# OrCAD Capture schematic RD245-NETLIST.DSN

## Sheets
1 2: size A3
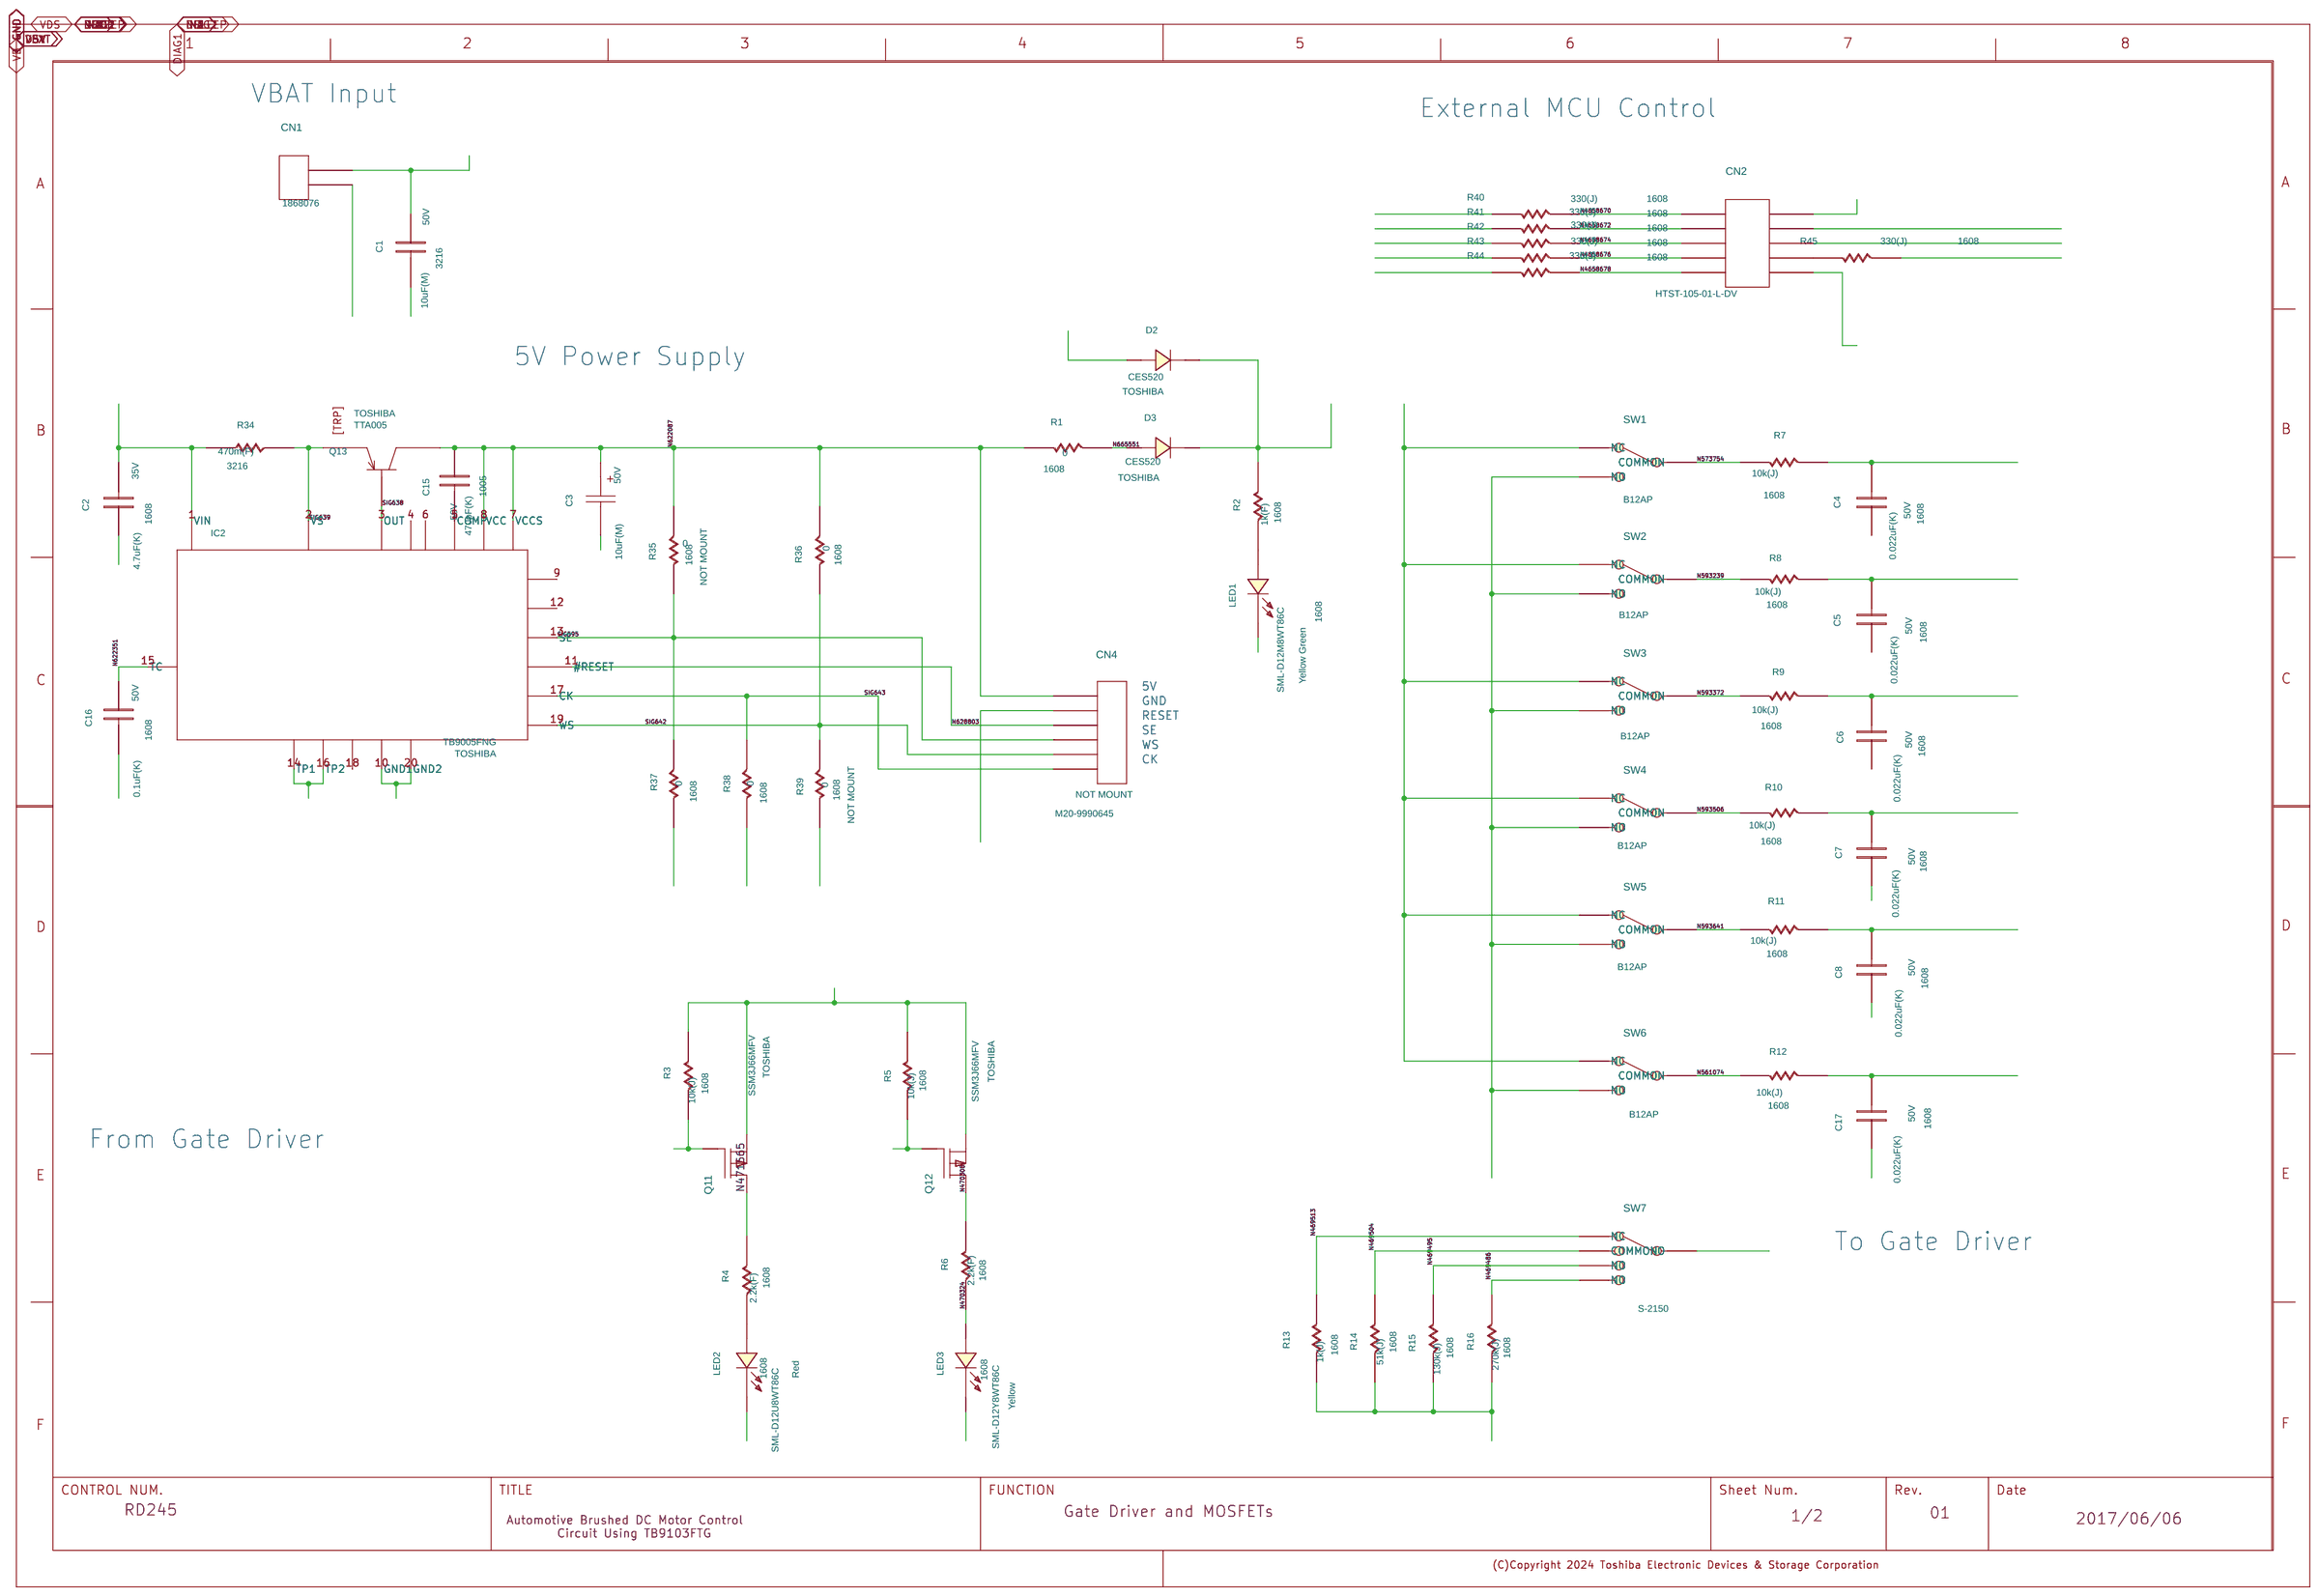
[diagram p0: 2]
2 1: size A3
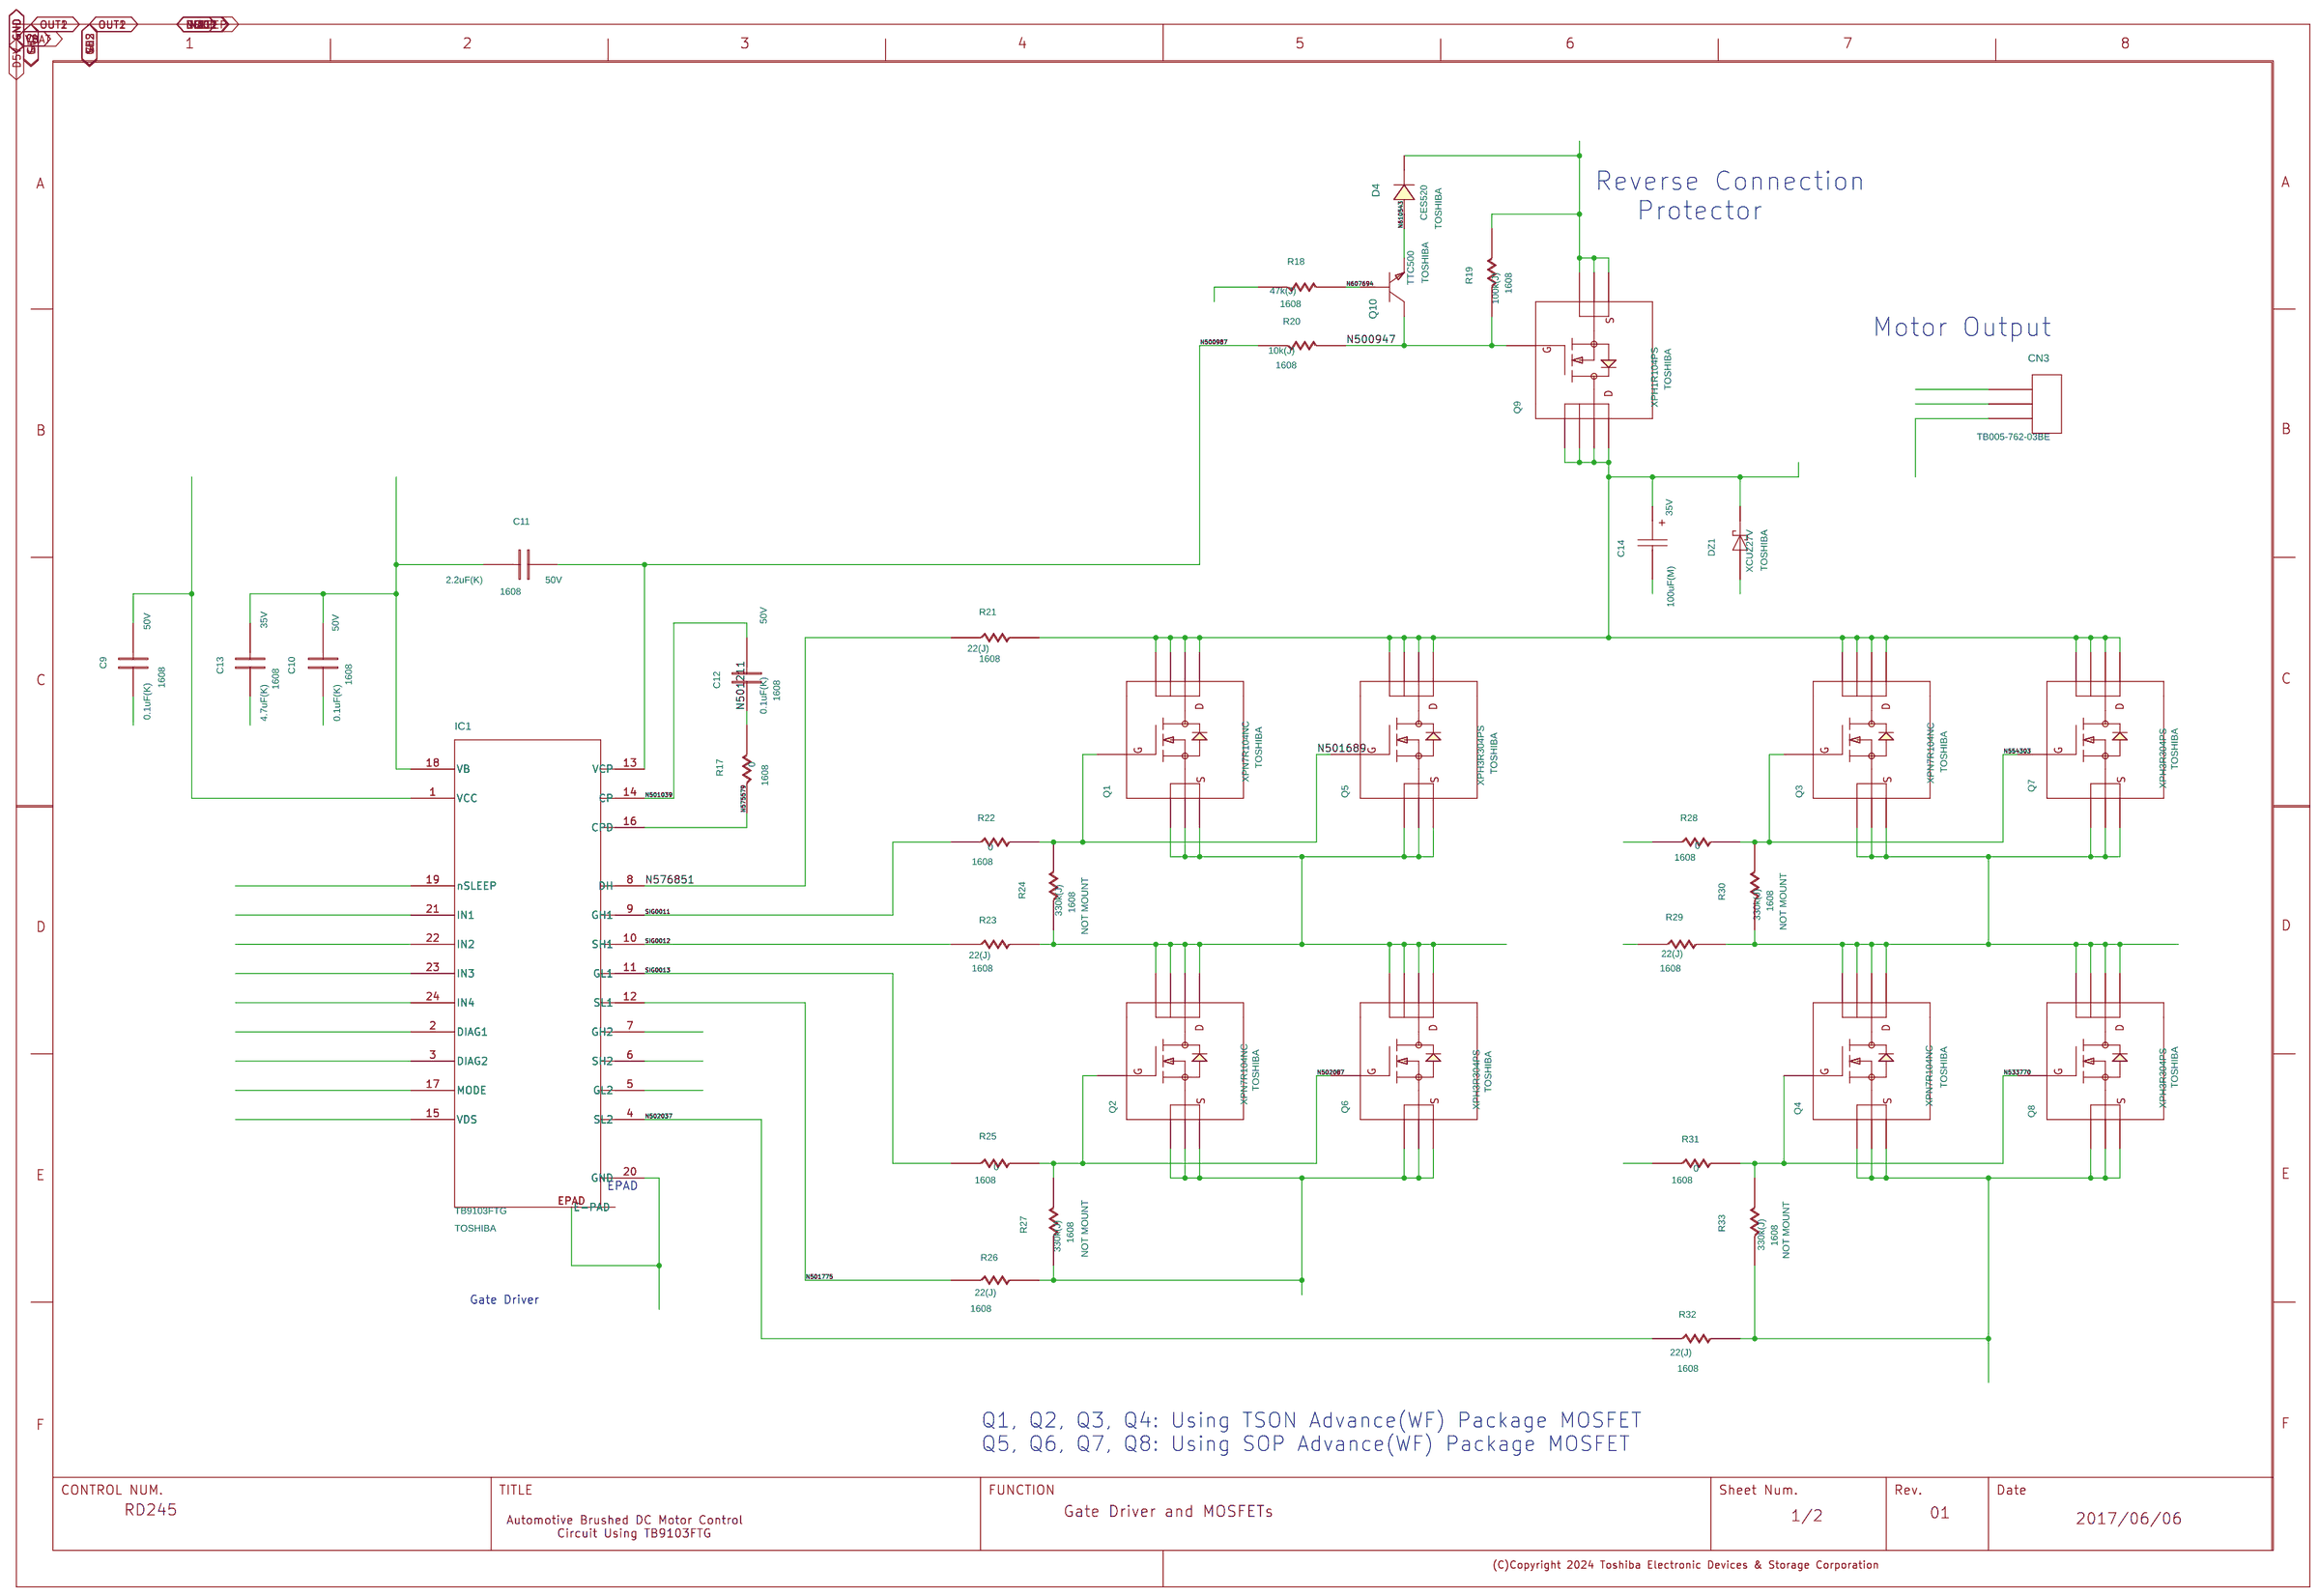
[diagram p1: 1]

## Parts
sheet 1
C9  C
C10  C
C11  C
C12  C
C13  C
C14  CP
CN3  TERMINAL-3P
D4  SBD
DZ1  SBD
IC1  TC241_3
Q1  MFNAC
Q2  MFNAC
Q3  MFNAC
Q4  MFNAC
Q5  MFNAC
Q6  MFNAC
Q7  MFNAC
Q8  MFNAC
Q9  MFNAC
Q10  BJT
R17  R
R18  R
R19  R
R20  R
R21  R
R22  R
R23  R
R24  R
R25  R
R26  R
R27  R
R28  R
R29  R
R30  R
R31  R
R32  R
R33  R
U?#1  WAKU_DEF100
sheet 2
C1  C
C2  C
C3  CP
C4  C
C5  C
C6  C
C7  C
C8  C
C15  C
C16  C
C17  C
CN1  TERMINAL-2P
CN2  PINHEADER-2x10
CN4  PINHEADER-1x6
D2  SBD
D3  SBD
IC2  TB9005FNG
LED1  LED
LED2  LED
LED3  LED
Q11  MOSFET
Q12  MOSFET
Q13  TRP
R1  R
R2  R
R3  R
R4  R
R5  R
R6  R
R7  R
R8  R
R9  R
R10  R
R11  R
R12  R
R13  R
R14  R
R15  R
R16  R
R34  R
R35  R
R36  R
R37  R
R38  R
R39  R
R40  R
R41  R
R42  R
R43  R
R44  R
R45  R
SW1  SW KEY-SPDT
SW2  SW KEY-SPDT
SW3  SW KEY-SPDT
SW4  SW KEY-SPDT
SW5  SW KEY-SPDT
SW6  SW KEY-SPDT
SW7  SW KEY-SPDT
U?#2  WAKU_DEF100

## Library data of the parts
C9 = C: ADSMODELNAME: s_ZRB18AR61E106ME01L; CAPACITANCETOLE: M; CDMASTERCADCELG: KC0167; CHIPSIZE: 1608; COMPONENTKIND: 0; COMPONENTNAME: C_C; COMPONENTTYPE: 4; FNLEADFREETHET1GT2GMCTH1: N_N_N; FUNCN: C_C; GCOUNT: 1; INSTANCENAME: INS530329; MAKER: TDK; MAXGCOUNT: 1; NOMINALCAPACITA: 10u; OUMECLASSIFICATION: ƒZƒ‰ƒ~ƒbƒNƒRƒ“ƒfƒ“ƒT; OUMEMAKER: MRT ºc»ì; OUMEMAKERKATAMEI: ZRB18AR61E106ME01L; QUADMODEL: CON_10U; RATEDVOLTAGE: 25; SIZECODESMD: 1608; TIME: 17:22:43; UPDATEDATE: 2021/07/08; UPDATETIME: 17:22:43; VAL1: 0.1uF(K); VAL2: 50V; VAL3: GCM188R71H104KA57J; VAL4: Murata
C10 = C: ADSMODELNAME: s_ZRB18AR61E106ME01L; CAPACITANCETOLE: M; CDMASTERCADCELG: KC0167; CHIPSIZE: 1608; COMPONENTKIND: 0; COMPONENTNAME: C_C; COMPONENTTYPE: 4; FNLEADFREETHET1GT2GMCTH1: N_N_N; FUNCN: C_C; GCOUNT: 1; INSTANCENAME: INS530425; MAKER: TDK; MAXGCOUNT: 1; NOMINALCAPACITA: 10u; OUMECLASSIFICATION: ƒZƒ‰ƒ~ƒbƒNƒRƒ“ƒfƒ“ƒT; OUMEMAKER: MRT ºc»ì; OUMEMAKERKATAMEI: ZRB18AR61E106ME01L; QUADMODEL: CON_10U; RATEDVOLTAGE: 25; SIZECODESMD: 1608; TIME: 17:22:43; UPDATEDATE: 2021/07/08; UPDATETIME: 17:22:43; VAL1: 0.1uF(K); VAL2: 50V; VAL3: GCM188R71H104KA57J; VAL4: Murata
C11 = C: ADSMODELNAME: s_ZRB18AR61E106ME01L; CAPACITANCETOLE: M; CDMASTERCADCELG: KC0167; CHIPSIZE: 1608; COMPONENTKIND: 0; COMPONENTNAME: C_C; COMPONENTTYPE: 4; FNLEADFREETHET1GT2GMCTH1: N_N_N; FUNCN: C_C; GCOUNT: 1; INSTANCENAME: INS530173; MAKER: TDK; MAXGCOUNT: 1; NOMINALCAPACITA: 10u; OUMECLASSIFICATION: ƒZƒ‰ƒ~ƒbƒNƒRƒ“ƒfƒ“ƒT; OUMEMAKER: MRT ºc»ì; OUMEMAKERKATAMEI: ZRB18AR61E106ME01L; QUADMODEL: CON_10U; RATEDVOLTAGE: 25; SIZECODESMD: 1608; TIME: 17:22:43; UPDATEDATE: 2021/07/08; UPDATETIME: 17:22:43; VAL1: 2.2uF(K); VAL2: 50V; VAL3: GRT188R61H225KE13D; VAL4: Murata
C12 = C: ADSMODELNAME: s_ZRB18AR61E106ME01L; CAPACITANCETOLE: M; CDMASTERCADCELG: KC0167; CHIPSIZE: 1608; COMPONENTKIND: 0; COMPONENTNAME: C_C; COMPONENTTYPE: 4; FNLEADFREETHET1GT2GMCTH1: N_N_N; FUNCN: C_C; GCOUNT: 1; INSTANCENAME: INS529943; MAKER: TDK; MAXGCOUNT: 1; NOMINALCAPACITA: 10u; OUMECLASSIFICATION: ƒZƒ‰ƒ~ƒbƒNƒRƒ“ƒfƒ“ƒT; OUMEMAKER: MRT ºc»ì; OUMEMAKERKATAMEI: ZRB18AR61E106ME01L; QUADMODEL: CON_10U; RATEDVOLTAGE: 25; SIZECODESMD: 1608; TIME: 17:22:43; UPDATEDATE: 2021/07/08; UPDATETIME: 17:22:43; VAL1: 0.1uF(K); VAL2: 50V; VAL3: GCM188R71H104KA57J; VAL4: Murata
C13 = C: ADSMODELNAME: s_ZRB18AR61E106ME01L; CAPACITANCETOLE: M; CDMASTERCADCELG: KC0167; CHIPSIZE: 1608; COMPONENTKIND: 0; COMPONENTNAME: C_C; COMPONENTTYPE: 4; FNLEADFREETHET1GT2GMCTH1: N_N_N; FUNCN: C_C; GCOUNT: 1; INSTANCENAME: INS647841; MAKER: TDK; MAXGCOUNT: 1; NOMINALCAPACITA: 10u; OUMECLASSIFICATION: ƒZƒ‰ƒ~ƒbƒNƒRƒ“ƒfƒ“ƒT; OUMEMAKER: MRT ºc»ì; OUMEMAKERKATAMEI: ZRB18AR61E106ME01L; QUADMODEL: CON_10U; RATEDVOLTAGE: 25; SIZECODESMD: 1608; TIME: 17:22:43; UPDATEDATE: 2021/07/08; UPDATETIME: 17:22:43; VAL1: 4.7uF(K); VAL2: 35V; VAL3: GRT188R6YA475KE13D; VAL4: Murata
C14 = CP: CAPACITANCETOLE: M; CDMASTERCADCELG: DC213N; CHIPSIZE: D35xL30; COMPONENTKIND: 0; COMPONENTNAME: CP_CP; COMPONENTTYPE: 4; FNLEADFREETHET1GT2GMCTH1: 9_N_N; FUNCN: CP_CP; GCOUNT: 1; INSTANCENAME: INS636800; MAKER: RUBYCON; MAXGCOUNT: 1; NOMINALCAPACITA: 330u; OUMECLASSIFICATION: ƒAƒ‹ƒ~“d‰ðƒRƒ“ƒfƒ“ƒT; OUMEMAKER: SIT ƒ‹ƒrƒRƒ“; OUMEMAKERKATAMEI: 450MXC330M35X40; OUMEPARTTYPE: C; QUADMODEL: CON_330U; RATEDVOLTAGE: 450; SAVECOUNT: 52; SIZECODESMD: DIP; TIME: 15:02:55; UPDATEDATE: 2006/10/03; UPDATETIME: 16:13:42; UPDATEUSER: fukuda-y; VAL1: 100uF(M); VAL2: 35V; VAL3: HHXD350ARA101MHA0G; VAL4: Chemi-Con
CN3 = CON3: COMPONENTKIND: 134; COMPONENTNAME: CON3_CON3; COMPONENTTYPE: 4; FUNCN: CON3_CON3; INSTANCENAME: INS530345; VAL2: 300V/30A; VAL3: TB005-762-03BE; VAL4: CUI Devices
D4 = DIODE_0: COMPONENTKIND: 103; COMPONENTNAME: DIODE_0_DIODE_0; COMPONENTTYPE: 4; FUNCN: DIODE_0_DIODE_0; INSTANCENAME: INS530245; USERCOMPTEXT3: TOSHIBA; VAL3: CES520; VAL4: TOSHIBA
DZ1 = SBD: COMPONENTKIND: 0; COMPONENTNAME: SBD_SBD; COMPONENTTYPE: 4; FUNCN: SBD_SBD; INSTANCENAME: INS530189; MAKER: TOSHIBA; TIME: 14:49:55; UPDATEDATE: 2006/10/04; UPDATETIME: 08:16:22; UPDATEUSER: fukuda-y; USERCOMPTEXT3: TOSHIBA; VAL3: XCUZ27V; VAL4: TOSHIBA
IC1 = TC241_3: COMPONENTKIND: 0; COMPONENTNAME: TC241_3_Graphic_Schematic_1_package; COMPONENTTYPE: 4; FUNCN: TC241_3_Graphic_Schematic_1_package; INSTANCENAME: cmp65; USERCOMPTEXT3: TOSHIBA; VAL1: GATE_DRIVER; VAL3: TB9103FTG
Q1 = MFNAC_23: COMPONENTKIND: 0; COMPONENTNAME: MFNAC_23_MFNAC_23; COMPONENTTYPE: 4; FUNCN: MFNAC_23_MFNAC_23; INSTANCENAME: INS529903; MAKER: TOSHIBA; TIME: 18:29:30; UPDATEDATE: 2008/08/26; UPDATETIME: 14:45:16; UPDATEUSER: 19990028; USERCOMPTEXT3: TOSHIBA; VAL3: XPN7R104NC; VAL4: TOSHIBA
Q2 = MFNAC_23: COMPONENTKIND: 0; COMPONENTNAME: MFNAC_23_MFNAC_23; COMPONENTTYPE: 4; FUNCN: MFNAC_23_MFNAC_23; INSTANCENAME: INS530205; MAKER: TOSHIBA; TIME: 18:29:30; UPDATEDATE: 2008/08/26; UPDATETIME: 14:45:16; UPDATEUSER: 19990028; USERCOMPTEXT3: TOSHIBA; VAL3: XPN7R104NC; VAL4: TOSHIBA
Q3 = MFNAC_23: COMPONENTKIND: 0; COMPONENTNAME: MFNAC_23_MFNAC_23; COMPONENTTYPE: 4; FUNCN: MFNAC_23_MFNAC_23; INSTANCENAME: INS533486; MAKER: TOSHIBA; TIME: 18:29:30; UPDATEDATE: 2008/08/26; UPDATETIME: 14:45:16; UPDATEUSER: 19990028; USERCOMPTEXT3: TOSHIBA; VAL3: XPN7R104NC; VAL4: TOSHIBA
Q4 = MFNAC_23: COMPONENTKIND: 0; COMPONENTNAME: MFNAC_23_MFNAC_23; COMPONENTTYPE: 4; FUNCN: MFNAC_23_MFNAC_23; INSTANCENAME: INS533696; MAKER: TOSHIBA; TIME: 18:29:30; UPDATEDATE: 2008/08/26; UPDATETIME: 14:45:16; UPDATEUSER: 19990028; USERCOMPTEXT3: TOSHIBA; VAL3: XPN7R104NC; VAL4: TOSHIBA
Q5 = MFNAC_23: COMPONENTKIND: 0; COMPONENTNAME: MFNAC_23_MFNAC_23; COMPONENTTYPE: 4; FUNCN: MFNAC_23_MFNAC_23; INSTANCENAME: INS530025; MAKER: TOSHIBA; TIME: 18:29:30; UPDATEDATE: 2008/08/26; UPDATETIME: 14:45:16; UPDATEUSER: 19990028; USERCOMPTEXT3: TOSHIBA; VAL3: XPH3R304PS; VAL4: TOSHIBA
Q6 = MFNAC_23: COMPONENTKIND: 0; COMPONENTNAME: MFNAC_23_MFNAC_23; COMPONENTTYPE: 4; FUNCN: MFNAC_23_MFNAC_23; INSTANCENAME: INS530385; MAKER: TOSHIBA; TIME: 18:29:30; UPDATEDATE: 2008/08/26; UPDATETIME: 14:45:16; UPDATEUSER: 19990028; USERCOMPTEXT3: TOSHIBA; VAL3: XPH3R304PS; VAL4: TOSHIBA
Q7 = MFNAC_23: COMPONENTKIND: 0; COMPONENTNAME: MFNAC_23_MFNAC_23; COMPONENTTYPE: 4; FUNCN: MFNAC_23_MFNAC_23; INSTANCENAME: INS533510; MAKER: TOSHIBA; TIME: 18:29:30; UPDATEDATE: 2008/08/26; UPDATETIME: 14:45:16; UPDATEUSER: 19990028; USERCOMPTEXT3: TOSHIBA; VAL3: XPH3R304PS; VAL4: TOSHIBA
Q8 = MFNAC_23: COMPONENTKIND: 0; COMPONENTNAME: MFNAC_23_MFNAC_23; COMPONENTTYPE: 4; FUNCN: MFNAC_23_MFNAC_23; INSTANCENAME: INS533720; MAKER: TOSHIBA; TIME: 18:29:30; UPDATEDATE: 2008/08/26; UPDATETIME: 14:45:16; UPDATEUSER: 19990028; USERCOMPTEXT3: TOSHIBA; VAL3: XPH3R304PS; VAL4: TOSHIBA
Q9 = MFNAC_23: COMPONENTKIND: 0; COMPONENTNAME: MFNAC_23_MFNAC_23; COMPONENTTYPE: 4; FUNCN: MFNAC_23_MFNAC_23; INSTANCENAME: INS529983; MAKER: TOSHIBA; TIME: 18:29:30; UPDATEDATE: 2008/08/26; UPDATETIME: 14:45:16; UPDATEUSER: 19990028; USERCOMPTEXT3: TOSHIBA; VAL3: XPH1R104PS; VAL4: TOSHIBA
Q10 = 2N1069_0: COMPONENTKIND: 102; COMPONENTNAME: 2N1069_0_2N1069_0; COMPONENTTYPE: 4; FUNCN: 2N1069_0_2N1069_0; INSTANCENAME: INS529959; USERCOMPTEXT3: TOSHIBA; VAL3: TTC500; VAL4: TOSHIBA
R17 = R: ADSMODELNAME: s_RL1632H_R001_JN; CDMASTERCADCELG: KC0020; CHIPSIZE: 3216; COMPONENTKIND: 0; COMPONENTNAME: R_R; COMPONENTTYPE: 4; FNLEADFREETHET1GT2GMCTH1: N_N_N; FUNCN: R_R; GCOUNT: 1; INSTANCENAME: INS529855; MAKER: KOA; MAXGCOUNT: 1; MOUNTINGFORMSMD: SMD; NOMINALRESISTAN: 1m; OUMECLASSIFICATION: \ÊÀpÅèïRí; OUMEMAKER: SSM iHÆ; OUMEMAKERKATAMEI: RL1632H-R001-JN; POWERRATING: 500m; QUADMODEL: RES_1M; RESISTANCETOLER: J; SIZECODESMD: 1608; TIME: 17:22:43; UPDATEDATE: 2021/07/08; UPDATETIME: 17:22:43; VAL1: 0; VAL3: RK73Z1JTTD; VAL4: KOA
R18 = R: ADSMODELNAME: s_RL1632H_R001_JN; CDMASTERCADCELG: KC0020; CHIPSIZE: 3216; COMPONENTKIND: 0; COMPONENTNAME: R_R; COMPONENTTYPE: 4; FNLEADFREETHET1GT2GMCTH1: N_N_N; FUNCN: R_R; GCOUNT: 1; INSTANCENAME: INS529871; MAKER: KOA; MAXGCOUNT: 1; MOUNTINGFORMSMD: SMD; NOMINALRESISTAN: 1m; OUMECLASSIFICATION: \ÊÀpÅèïRí; OUMEMAKER: SSM iHÆ; OUMEMAKERKATAMEI: RL1632H-R001-JN; POWERRATING: 500m; QUADMODEL: RES_1M; RESISTANCETOLER: J; SIZECODESMD: 1608; TIME: 17:22:43; UPDATEDATE: 2021/07/08; UPDATETIME: 17:22:43; VAL1: 47k(J); VAL2: 100mW; VAL3: RK73B1JTTD473J; VAL4: KOA
R19 = R: ADSMODELNAME: s_RL1632H_R001_JN; CDMASTERCADCELG: KC0020; CHIPSIZE: 3216; COMPONENTKIND: 0; COMPONENTNAME: R_R; COMPONENTTYPE: 4; FNLEADFREETHET1GT2GMCTH1: N_N_N; FUNCN: R_R; GCOUNT: 1; INSTANCENAME: INS530265; MAKER: KOA; MAXGCOUNT: 1; MOUNTINGFORMSMD: SMD; NOMINALRESISTAN: 1m; OUMECLASSIFICATION: \ÊÀpÅèïRí; OUMEMAKER: SSM iHÆ; OUMEMAKERKATAMEI: RL1632H-R001-JN; POWERRATING: 500m; QUADMODEL: RES_1M; RESISTANCETOLER: J; SIZECODESMD: 1608; TIME: 17:22:43; UPDATEDATE: 2021/07/08; UPDATETIME: 17:22:43; VAL1: 100k(J); VAL2: 100mW; VAL3: RK73B1JTTD104J; VAL4: KOA
R20 = R: ADSMODELNAME: s_RL1632H_R001_JN; CDMASTERCADCELG: KC0020; CHIPSIZE: 3216; COMPONENTKIND: 0; COMPONENTNAME: R_R; COMPONENTTYPE: 4; FNLEADFREETHET1GT2GMCTH1: N_N_N; FUNCN: R_R; GCOUNT: 1; INSTANCENAME: INS529887; MAKER: KOA; MAXGCOUNT: 1; MOUNTINGFORMSMD: SMD; NOMINALRESISTAN: 1m; OUMECLASSIFICATION: \ÊÀpÅèïRí; OUMEMAKER: SSM iHÆ; OUMEMAKERKATAMEI: RL1632H-R001-JN; POWERRATING: 500m; QUADMODEL: RES_1M; RESISTANCETOLER: J; SIZECODESMD: 1608; TIME: 17:22:43; UPDATEDATE: 2021/07/08; UPDATETIME: 17:22:43; VAL1: 10k(J); VAL2: 100mW; VAL3: RK73B1JTTD103J; VAL4: KOA
R21 = R: ADSMODELNAME: s_RL1632H_R001_JN; CDMASTERCADCELG: KC0020; CHIPSIZE: 3216; COMPONENTKIND: 0; COMPONENTNAME: R_R; COMPONENTTYPE: 4; FNLEADFREETHET1GT2GMCTH1: N_N_N; FUNCN: R_R; GCOUNT: 1; INSTANCENAME: INS575614; MAKER: KOA; MAXGCOUNT: 1; MOUNTINGFORMSMD: SMD; NOMINALRESISTAN: 1m; OUMECLASSIFICATION: \ÊÀpÅèïRí; OUMEMAKER: SSM iHÆ; OUMEMAKERKATAMEI: RL1632H-R001-JN; POWERRATING: 500m; QUADMODEL: RES_1M; RESISTANCETOLER: J; SIZECODESMD: 1608; TIME: 17:22:43; UPDATEDATE: 2021/07/08; UPDATETIME: 17:22:43; VAL1: 22(J); VAL2: 125mW; VAL3: RK73B1JTTD220J; VAL4: KOA
R22 = R: ADSMODELNAME: s_RL1632H_R001_JN; CDMASTERCADCELG: KC0020; CHIPSIZE: 3216; COMPONENTKIND: 0; COMPONENTNAME: R_R; COMPONENTTYPE: 4; FNLEADFREETHET1GT2GMCTH1: N_N_N; FUNCN: R_R; GCOUNT: 1; INSTANCENAME: INS530281; MAKER: KOA; MAXGCOUNT: 1; MOUNTINGFORMSMD: SMD; NOMINALRESISTAN: 1m; OUMECLASSIFICATION: \ÊÀpÅèïRí; OUMEMAKER: SSM iHÆ; OUMEMAKERKATAMEI: RL1632H-R001-JN; POWERRATING: 500m; QUADMODEL: RES_1M; RESISTANCETOLER: J; SIZECODESMD: 1608; TIME: 17:22:43; UPDATEDATE: 2021/07/08; UPDATETIME: 17:22:43; VAL1: 0; VAL3: RK73Z1JTTD; VAL4: KOA
R23 = R: ADSMODELNAME: s_RL1632H_R001_JN; CDMASTERCADCELG: KC0020; CHIPSIZE: 3216; COMPONENTKIND: 0; COMPONENTNAME: R_R; COMPONENTTYPE: 4; FNLEADFREETHET1GT2GMCTH1: N_N_N; FUNCN: R_R; GCOUNT: 1; INSTANCENAME: INS577102; MAKER: KOA; MAXGCOUNT: 1; MOUNTINGFORMSMD: SMD; NOMINALRESISTAN: 1m; OUMECLASSIFICATION: \ÊÀpÅèïRí; OUMEMAKER: SSM iHÆ; OUMEMAKERKATAMEI: RL1632H-R001-JN; POWERRATING: 500m; QUADMODEL: RES_1M; RESISTANCETOLER: J; SIZECODESMD: 1608; TIME: 17:22:43; UPDATEDATE: 2021/07/08; UPDATETIME: 17:22:43; VAL1: 22(J); VAL2: 125mW; VAL3: RK73B1JTTD220J; VAL4: KOA
R24 = R: ADSMODELNAME: s_RL1632H_R001_JN; CDMASTERCADCELG: KC0020; CHIPSIZE: 3216; COMPONENTKIND: 0; COMPONENTNAME: R_R; COMPONENTTYPE: 4; FNLEADFREETHET1GT2GMCTH1: N_N_N; FUNCN: R_R; GCOUNT: 1; INSTANCENAME: INS586735; MAKER: KOA; MAXGCOUNT: 1; MOUNTINGFORMSMD: SMD; NOMINALRESISTAN: 1m; NOTMOUNT: NOT MOUNT; OUMECLASSIFICATION: \ÊÀpÅèïRí; OUMEMAKER: SSM iHÆ; OUMEMAKERKATAMEI: RL1632H-R001-JN; POWERRATING: 500m; QUADMODEL: RES_1M; RESISTANCETOLER: J; SIZECODESMD: 1608; TIME: 17:22:43; UPDATEDATE: 2021/07/08; UPDATETIME: 17:22:43; VAL1: 330k(J); VAL2: 100mW; VAL3: RK73B1JTTD334J; VAL4: KOA
R25 = R: ADSMODELNAME: s_RL1632H_R001_JN; CDMASTERCADCELG: KC0020; CHIPSIZE: 3216; COMPONENTKIND: 0; COMPONENTNAME: R_R; COMPONENTTYPE: 4; FNLEADFREETHET1GT2GMCTH1: N_N_N; FUNCN: R_R; GCOUNT: 1; INSTANCENAME: INS530297; MAKER: KOA; MAXGCOUNT: 1; MOUNTINGFORMSMD: SMD; NOMINALRESISTAN: 1m; OUMECLASSIFICATION: \ÊÀpÅèïRí; OUMEMAKER: SSM iHÆ; OUMEMAKERKATAMEI: RL1632H-R001-JN; POWERRATING: 500m; QUADMODEL: RES_1M; RESISTANCETOLER: J; SIZECODESMD: 1608; TIME: 17:22:43; UPDATEDATE: 2021/07/08; UPDATETIME: 17:22:43; VAL1: 0; VAL3: RK73Z1JTTD; VAL4: KOA
R26 = R: ADSMODELNAME: s_RL1632H_R001_JN; CDMASTERCADCELG: KC0020; CHIPSIZE: 3216; COMPONENTKIND: 0; COMPONENTNAME: R_R; COMPONENTTYPE: 4; FNLEADFREETHET1GT2GMCTH1: N_N_N; FUNCN: R_R; GCOUNT: 1; INSTANCENAME: INS577602; MAKER: KOA; MAXGCOUNT: 1; MOUNTINGFORMSMD: SMD; NOMINALRESISTAN: 1m; OUMECLASSIFICATION: \ÊÀpÅèïRí; OUMEMAKER: SSM iHÆ; OUMEMAKERKATAMEI: RL1632H-R001-JN; POWERRATING: 500m; QUADMODEL: RES_1M; RESISTANCETOLER: J; SIZECODESMD: 1608; TIME: 17:22:43; UPDATEDATE: 2021/07/08; UPDATETIME: 17:22:43; VAL1: 22(J); VAL2: 125mW; VAL3: RK73B1JTTD220J; VAL4: KOA
R27 = R: ADSMODELNAME: s_RL1632H_R001_JN; CDMASTERCADCELG: KC0020; CHIPSIZE: 3216; COMPONENTKIND: 0; COMPONENTNAME: R_R; COMPONENTTYPE: 4; FNLEADFREETHET1GT2GMCTH1: N_N_N; FUNCN: R_R; GCOUNT: 1; INSTANCENAME: INS591774; MAKER: KOA; MAXGCOUNT: 1; MOUNTINGFORMSMD: SMD; NOMINALRESISTAN: 1m; NOTMOUNT: NOT MOUNT; OUMECLASSIFICATION: \ÊÀpÅèïRí; OUMEMAKER: SSM iHÆ; OUMEMAKERKATAMEI: RL1632H-R001-JN; POWERRATING: 500m; QUADMODEL: RES_1M; RESISTANCETOLER: J; SIZECODESMD: 1608; TIME: 17:22:43; UPDATEDATE: 2021/07/08; UPDATETIME: 17:22:43; VAL1: 330k(J); VAL2: 100mW; VAL3: RK73B1JTTD334J; VAL4: KOA
R28 = R: ADSMODELNAME: s_RL1632H_R001_JN; CDMASTERCADCELG: KC0020; CHIPSIZE: 3216; COMPONENTKIND: 0; COMPONENTNAME: R_R; COMPONENTTYPE: 4; FNLEADFREETHET1GT2GMCTH1: N_N_N; FUNCN: R_R; GCOUNT: 1; INSTANCENAME: INS533534; MAKER: KOA; MAXGCOUNT: 1; MOUNTINGFORMSMD: SMD; NOMINALRESISTAN: 1m; OUMECLASSIFICATION: \ÊÀpÅèïRí; OUMEMAKER: SSM iHÆ; OUMEMAKERKATAMEI: RL1632H-R001-JN; POWERRATING: 500m; QUADMODEL: RES_1M; RESISTANCETOLER: J; SIZECODESMD: 1608; TIME: 17:22:43; UPDATEDATE: 2021/07/08; UPDATETIME: 17:22:43; VAL1: 0; VAL3: RK73Z1JTTD; VAL4: KOA
R29 = R: ADSMODELNAME: s_RL1632H_R001_JN; CDMASTERCADCELG: KC0020; CHIPSIZE: 3216; COMPONENTKIND: 0; COMPONENTNAME: R_R; COMPONENTTYPE: 4; FNLEADFREETHET1GT2GMCTH1: N_N_N; FUNCN: R_R; GCOUNT: 1; INSTANCENAME: INS579870; MAKER: KOA; MAXGCOUNT: 1; MOUNTINGFORMSMD: SMD; NOMINALRESISTAN: 1m; OUMECLASSIFICATION: \ÊÀpÅèïRí; OUMEMAKER: SSM iHÆ; OUMEMAKERKATAMEI: RL1632H-R001-JN; POWERRATING: 500m; QUADMODEL: RES_1M; RESISTANCETOLER: J; SIZECODESMD: 1608; TIME: 17:22:43; UPDATEDATE: 2021/07/08; UPDATETIME: 17:22:43; VAL1: 22(J); VAL2: 125mW; VAL3: RK73B1JTTD220J; VAL4: KOA
R30 = R: ADSMODELNAME: s_RL1632H_R001_JN; CDMASTERCADCELG: KC0020; CHIPSIZE: 3216; COMPONENTKIND: 0; COMPONENTNAME: R_R; COMPONENTTYPE: 4; FNLEADFREETHET1GT2GMCTH1: N_N_N; FUNCN: R_R; GCOUNT: 1; INSTANCENAME: INS592756; MAKER: KOA; MAXGCOUNT: 1; MOUNTINGFORMSMD: SMD; NOMINALRESISTAN: 1m; NOTMOUNT: NOT MOUNT; OUMECLASSIFICATION: \ÊÀpÅèïRí; OUMEMAKER: SSM iHÆ; OUMEMAKERKATAMEI: RL1632H-R001-JN; POWERRATING: 500m; QUADMODEL: RES_1M; RESISTANCETOLER: J; SIZECODESMD: 1608; TIME: 17:22:43; UPDATEDATE: 2021/07/08; UPDATETIME: 17:22:43; VAL1: 330k(J); VAL2: 100mW; VAL3: RK73B1JTTD334J; VAL4: KOA
R31 = R: ADSMODELNAME: s_RL1632H_R001_JN; CDMASTERCADCELG: KC0020; CHIPSIZE: 3216; COMPONENTKIND: 0; COMPONENTNAME: R_R; COMPONENTTYPE: 4; FNLEADFREETHET1GT2GMCTH1: N_N_N; FUNCN: R_R; GCOUNT: 1; INSTANCENAME: INS533744; MAKER: KOA; MAXGCOUNT: 1; MOUNTINGFORMSMD: SMD; NOMINALRESISTAN: 1m; OUMECLASSIFICATION: \ÊÀpÅèïRí; OUMEMAKER: SSM iHÆ; OUMEMAKERKATAMEI: RL1632H-R001-JN; POWERRATING: 500m; QUADMODEL: RES_1M; RESISTANCETOLER: J; SIZECODESMD: 1608; TIME: 17:22:43; UPDATEDATE: 2021/07/08; UPDATETIME: 17:22:43; VAL1: 0; VAL3: RK73Z1JTTD; VAL4: KOA
R32 = R: ADSMODELNAME: s_RL1632H_R001_JN; CDMASTERCADCELG: KC0020; CHIPSIZE: 3216; COMPONENTKIND: 0; COMPONENTNAME: R_R; COMPONENTTYPE: 4; FNLEADFREETHET1GT2GMCTH1: N_N_N; FUNCN: R_R; GCOUNT: 1; INSTANCENAME: INS577624; MAKER: KOA; MAXGCOUNT: 1; MOUNTINGFORMSMD: SMD; NOMINALRESISTAN: 1m; OUMECLASSIFICATION: \ÊÀpÅèïRí; OUMEMAKER: SSM iHÆ; OUMEMAKERKATAMEI: RL1632H-R001-JN; POWERRATING: 500m; QUADMODEL: RES_1M; RESISTANCETOLER: J; SIZECODESMD: 1608; TIME: 17:22:43; UPDATEDATE: 2021/07/08; UPDATETIME: 17:22:43; VAL1: 22(J); VAL2: 125mW; VAL3: RK73B1JTTD220J; VAL4: KOA
R33 = R: ADSMODELNAME: s_RL1632H_R001_JN; CDMASTERCADCELG: KC0020; CHIPSIZE: 3216; COMPONENTKIND: 0; COMPONENTNAME: R_R; COMPONENTTYPE: 4; FNLEADFREETHET1GT2GMCTH1: N_N_N; FUNCN: R_R; GCOUNT: 1; INSTANCENAME: INS592511; MAKER: KOA; MAXGCOUNT: 1; MOUNTINGFORMSMD: SMD; NOMINALRESISTAN: 1m; NOTMOUNT: NOT MOUNT; OUMECLASSIFICATION: \ÊÀpÅèïRí; OUMEMAKER: SSM iHÆ; OUMEMAKERKATAMEI: RL1632H-R001-JN; POWERRATING: 500m; QUADMODEL: RES_1M; RESISTANCETOLER: J; SIZECODESMD: 1608; TIME: 17:22:43; UPDATEDATE: 2021/07/08; UPDATETIME: 17:22:43; VAL1: 330k(J); VAL2: 100mW; VAL3: RK73B1JTTD334J; VAL4: KOA
U?#1 = WAKU_DEF100_1: AUTHOR: t5459927; COMPONENTTYPE: 2; DATE: 2017/06/06; DESIGNED: TOSHIBA; DRAWINGNUMBER: RD245; FUNCTION: Gate Driver and MOSFETs; INSTANCENAME: INS636826; PAGENUMBER: 8; REVISION: 01; SHEETNUMBER: 1/2; SHTSAVECOUNT: 37; TITLE: Automotive Brushed DC Motor Control / Circuit Using TB9103FTG; UPDATEDATE: 2024/10/02; UPDATETIME: 10:40:02; UPDATEUSER: sptcae09
C1 = C: CDBNAME: C0805K_2; COMPONENTKIND: 0; COMPONENTNAME: C_C; COMPONENTTYPE: 4; FUNCN: C_C; INSTANCENAME: cmp141; SIZECODESMD: 3216; TIME: 17:22:43; UPDATEDATE: 2021/07/08; UPDATETIME: 17:22:43; VAL1: 10uF(M); VAL2: 50V; VAL3: GRT31CR61H106ME01L; VAL4: Murata
C2 = C: ADSMODELNAME: s_ZRB18AR61E106ME01L; CAPACITANCETOLE: M; CDMASTERCADCELG: KC0167; CHIPSIZE: 1608; COMPONENTKIND: 0; COMPONENTNAME: C_C; COMPONENTTYPE: 4; FNLEADFREETHET1GT2GMCTH1: N_N_N; FUNCN: C_C; GCOUNT: 1; INSTANCENAME: INS669941; MAKER: TDK; MAXGCOUNT: 1; NOMINALCAPACITA: 10u; OUMECLASSIFICATION: ƒZƒ‰ƒ~ƒbƒNƒRƒ“ƒfƒ“ƒT; OUMEMAKER: MRT ºc»ì; OUMEMAKERKATAMEI: ZRB18AR61E106ME01L; QUADMODEL: CON_10U; RATEDVOLTAGE: 25; SIZECODESMD: 1608; TIME: 17:22:43; UPDATEDATE: 2021/07/08; UPDATETIME: 17:22:43; VAL1: 4.7uF(K); VAL2: 35V; VAL3: GRT188R6YA475KE13D; VAL4: Murata
C3 = CP: CAPACITANCETOLE: M; CDMASTERCADCELG: DC213N; CHIPSIZE: D35xL30; COMPONENTKIND: 0; COMPONENTNAME: CP_CP; COMPONENTTYPE: 4; FNLEADFREETHET1GT2GMCTH1: 9_N_N; FUNCN: CP_CP; GCOUNT: 1; INSTANCENAME: INS634215; MAKER: RUBYCON; MAXGCOUNT: 1; NOMINALCAPACITA: 330u; OUMECLASSIFICATION: ƒAƒ‹ƒ~“d‰ðƒRƒ“ƒfƒ“ƒT; OUMEMAKER: SIT ƒ‹ƒrƒRƒ“; OUMEMAKERKATAMEI: 450MXC330M35X40; OUMEPARTTYPE: C; QUADMODEL: CON_330U; RATEDVOLTAGE: 450; SAVECOUNT: 52; SIZECODESMD: DIP; TIME: 15:02:55; UPDATEDATE: 2006/10/03; UPDATETIME: 16:13:42; UPDATEUSER: fukuda-y; VAL1: 10uF(M); VAL2: 50V; VAL3: HHXD500ARA100MF61G; VAL4: Chemi-Con
C4 = C: ADSMODELNAME: s_ZRB18AR61E106ME01L; CAPACITANCETOLE: M; CDMASTERCADCELG: KC0167; CHIPSIZE: 1608; COMPONENTKIND: 0; COMPONENTNAME: C_C; COMPONENTTYPE: 4; FNLEADFREETHET1GT2GMCTH1: N_N_N; FUNCN: C_C; GCOUNT: 1; INSTANCENAME: INS573773; MAKER: TDK; MAXGCOUNT: 1; NOMINALCAPACITA: 10u; OUMECLASSIFICATION: ƒZƒ‰ƒ~ƒbƒNƒRƒ“ƒfƒ“ƒT; OUMEMAKER: MRT ºc»ì; OUMEMAKERKATAMEI: ZRB18AR61E106ME01L; QUADMODEL: CON_10U; RATEDVOLTAGE: 25; SIZECODESMD: 1608; TIME: 17:22:43; UPDATEDATE: 2021/07/08; UPDATETIME: 17:22:43; VAL1: 0.022uF(K); VAL2: 50V; VAL3: GCM188R91H223KA37D; VAL4: Murata
C5 = C: ADSMODELNAME: s_ZRB18AR61E106ME01L; CAPACITANCETOLE: M; CDMASTERCADCELG: KC0167; CHIPSIZE: 1608; COMPONENTKIND: 0; COMPONENTNAME: C_C; COMPONENTTYPE: 4; FNLEADFREETHET1GT2GMCTH1: N_N_N; FUNCN: C_C; GCOUNT: 1; INSTANCENAME: INS658183; MAKER: TDK; MAXGCOUNT: 1; NOMINALCAPACITA: 10u; OUMECLASSIFICATION: ƒZƒ‰ƒ~ƒbƒNƒRƒ“ƒfƒ“ƒT; OUMEMAKER: MRT ºc»ì; OUMEMAKERKATAMEI: ZRB18AR61E106ME01L; QUADMODEL: CON_10U; RATEDVOLTAGE: 25; SIZECODESMD: 1608; TIME: 17:22:43; UPDATEDATE: 2021/07/08; UPDATETIME: 17:22:43; VAL1: 0.022uF(K); VAL2: 50V; VAL3: GCM188R91H223KA37D; VAL4: Murata
C6 = C: ADSMODELNAME: s_ZRB18AR61E106ME01L; CAPACITANCETOLE: M; CDMASTERCADCELG: KC0167; CHIPSIZE: 1608; COMPONENTKIND: 0; COMPONENTNAME: C_C; COMPONENTTYPE: 4; FNLEADFREETHET1GT2GMCTH1: N_N_N; FUNCN: C_C; GCOUNT: 1; INSTANCENAME: INS658285; MAKER: TDK; MAXGCOUNT: 1; NOMINALCAPACITA: 10u; OUMECLASSIFICATION: ƒZƒ‰ƒ~ƒbƒNƒRƒ“ƒfƒ“ƒT; OUMEMAKER: MRT ºc»ì; OUMEMAKERKATAMEI: ZRB18AR61E106ME01L; QUADMODEL: CON_10U; RATEDVOLTAGE: 25; SIZECODESMD: 1608; TIME: 17:22:43; UPDATEDATE: 2021/07/08; UPDATETIME: 17:22:43; VAL1: 0.022uF(K); VAL2: 50V; VAL3: GCM188R91H223KA37D; VAL4: Murata
C7 = C: ADSMODELNAME: s_ZRB18AR61E106ME01L; CAPACITANCETOLE: M; CDMASTERCADCELG: KC0167; CHIPSIZE: 1608; COMPONENTKIND: 0; COMPONENTNAME: C_C; COMPONENTTYPE: 4; FNLEADFREETHET1GT2GMCTH1: N_N_N; FUNCN: C_C; GCOUNT: 1; INSTANCENAME: INS658387; MAKER: TDK; MAXGCOUNT: 1; NOMINALCAPACITA: 10u; OUMECLASSIFICATION: ƒZƒ‰ƒ~ƒbƒNƒRƒ“ƒfƒ“ƒT; OUMEMAKER: MRT ºc»ì; OUMEMAKERKATAMEI: ZRB18AR61E106ME01L; QUADMODEL: CON_10U; RATEDVOLTAGE: 25; SIZECODESMD: 1608; TIME: 17:22:43; UPDATEDATE: 2021/07/08; UPDATETIME: 17:22:43; VAL1: 0.022uF(K); VAL2: 50V; VAL3: GCM188R91H223KA37D; VAL4: Murata
C8 = C: ADSMODELNAME: s_ZRB18AR61E106ME01L; CAPACITANCETOLE: M; CDMASTERCADCELG: KC0167; CHIPSIZE: 1608; COMPONENTKIND: 0; COMPONENTNAME: C_C; COMPONENTTYPE: 4; FNLEADFREETHET1GT2GMCTH1: N_N_N; FUNCN: C_C; GCOUNT: 1; INSTANCENAME: INS658489; MAKER: TDK; MAXGCOUNT: 1; NOMINALCAPACITA: 10u; OUMECLASSIFICATION: ƒZƒ‰ƒ~ƒbƒNƒRƒ“ƒfƒ“ƒT; OUMEMAKER: MRT ºc»ì; OUMEMAKERKATAMEI: ZRB18AR61E106ME01L; QUADMODEL: CON_10U; RATEDVOLTAGE: 25; SIZECODESMD: 1608; TIME: 17:22:43; UPDATEDATE: 2021/07/08; UPDATETIME: 17:22:43; VAL1: 0.022uF(K); VAL2: 50V; VAL3: GCM188R91H223KA37D; VAL4: Murata
C15 = C: CDBNAME: C0805K_2; COMPONENTKIND: 0; COMPONENTNAME: C_C; COMPONENTTYPE: 4; FUNCN: C_C; INSTANCENAME: cmp141; SIZECODESMD: 1005; TIME: 17:22:43; UPDATEDATE: 2021/07/08; UPDATETIME: 17:22:43; VAL1: 470pF(K); VAL2: 50V; VAL3: GCM155R71H471KA37J; VAL4: Murata
C16 = C: CDBNAME: C0805K_3; COMPONENTKIND: 0; COMPONENTNAME: C_C; COMPONENTTYPE: 4; FUNCN: C_C; INSTANCENAME: cmp152; SIZECODESMD: 1608; TIME: 17:22:43; UPDATEDATE: 2021/07/08; UPDATETIME: 17:22:43; VAL1: 0.1uF(K); VAL2: 50V; VAL3: GCM188R71H104KA57J; VAL4: Murata
C17 = C: ADSMODELNAME: s_ZRB18AR61E106ME01L; CAPACITANCETOLE: M; CDMASTERCADCELG: KC0167; CHIPSIZE: 1608; COMPONENTKIND: 0; COMPONENTNAME: C_C; COMPONENTTYPE: 4; FNLEADFREETHET1GT2GMCTH1: N_N_N; FUNCN: C_C; GCOUNT: 1; INSTANCENAME: INS658591; MAKER: TDK; MAXGCOUNT: 1; NOMINALCAPACITA: 10u; OUMECLASSIFICATION: ƒZƒ‰ƒ~ƒbƒNƒRƒ“ƒfƒ“ƒT; OUMEMAKER: MRT ºc»ì; OUMEMAKERKATAMEI: ZRB18AR61E106ME01L; QUADMODEL: CON_10U; RATEDVOLTAGE: 25; SIZECODESMD: 1608; TIME: 17:22:43; UPDATEDATE: 2021/07/08; UPDATETIME: 17:22:43; VAL1: 0.022uF(K); VAL2: 50V; VAL3: GCM188R91H223KA37D; VAL4: Murata
CN1 = CON2: COMPONENTKIND: 134; COMPONENTNAME: CON2_CON2; COMPONENTTYPE: 4; FUNCN: CON2_CON2; INSTANCENAME: INS451962; VAL2: 500V/32A; VAL3: 1868076; VAL4: Phoenix
CN2 = CON10A: COMPONENTKIND: 134; COMPONENTNAME: CON10A_CON10A; COMPONENTTYPE: 4; FUNCN: CON10A_CON10A; INSTANCENAME: INS465841; VAL3: HTST-105-01-L-DV; VAL4: Samtec
CN4 = CON6: COMPONENTKIND: 134; COMPONENTNAME: CON6_CON6; COMPONENTTYPE: 4; FUNCN: CON6_CON6; INSTANCENAME: INS655764; NOTMOUNT: NOT MOUNT; VAL3: M20-9990645; VAL4: Harwin
D2 = DIODE_0: COMPONENTKIND: 103; COMPONENTNAME: DIODE_0_DIODE_0; COMPONENTTYPE: 4; FUNCN: DIODE_0_DIODE_0; INSTANCENAME: INS572955; USERCOMPTEXT3: TOSHIBA; VAL3: CES520; VAL4: TOSHIBA
D3 = DIODE_0: COMPONENTKIND: 103; COMPONENTNAME: DIODE_0_DIODE_0; COMPONENTTYPE: 4; FUNCN: DIODE_0_DIODE_0; INSTANCENAME: INS573569; USERCOMPTEXT3: TOSHIBA; VAL3: CES520; VAL4: TOSHIBA
IC2 = TB9005FNG_1: COMPONENTKIND: 0; COMPONENTNAME: TB9005FNG_1_TB9005FNG_1; COMPONENTTYPE: 4; FUNCN: TB9005FNG_1_TB9005FNG_1; INSTANCENAME: INS622199; SAVECOUNT: 3; TIME: 17:22:42; UPDATEDATE: 2021/07/13; UPDATETIME: 09:48:39; USERCOMPTEXT3: TOSHIBA; VAL1: LINEAR IC; VAL4: TOSHIBA
LED1 = LED_2: COMPONENTKIND: 103; COMPONENTNAME: LED_2_LED_2; COMPONENTTYPE: 4; FUNCN: LED_2_LED_2; INSTANCENAME: INS453112; SIZECODESMD: 1608; VAL1: Yellow Green; VAL3: SML-D12M8WT86C; VAL4: Rohm
LED2 = LED_2: COMPONENTKIND: 103; COMPONENTNAME: LED_2_LED_2; COMPONENTTYPE: 4; FUNCN: LED_2_LED_2; INSTANCENAME: INS496113; SIZECODESMD: 1608; VAL1: Red; VAL3: SML-D12U8WT86C; VAL4: Rohm
LED3 = LED_2: COMPONENTKIND: 103; COMPONENTNAME: LED_2_LED_2; COMPONENTTYPE: 4; FUNCN: LED_2_LED_2; INSTANCENAME: INS496225; SIZECODESMD: 1608; VAL1: Yellow; VAL3: SML-D12Y8WT86C; VAL4: Rohm
Q11 = ZVP0545_TO_0: COMPONENTKIND: 102; COMPONENTNAME: ZVP0545_TO_0_ZVP0545_TO_0; COMPONENTTYPE: 4; FUNCN: ZVP0545_TO_0_ZVP0545_TO_0; INSTANCENAME: INS493920; USERCOMPTEXT3: TOSHIBA; VAL3: SSM3J66MFV; VAL4: TOSHIBA
Q12 = ZVP0545_TO_0: COMPONENTKIND: 102; COMPONENTNAME: ZVP0545_TO_0_ZVP0545_TO_0; COMPONENTTYPE: 4; FUNCN: ZVP0545_TO_0_ZVP0545_TO_0; INSTANCENAME: INS494083; USERCOMPTEXT3: TOSHIBA; VAL3: SSM3J66MFV; VAL4: TOSHIBA
Q13 = TRP: CDBNAME: TTA005; COMPONENTKIND: 0; COMPONENTNAME: TRP_TRP; COMPONENTTYPE: 4; FUNCN: TRP_TRP; INSTANCENAME: cmp138; TIME: 17:22:43; UPDATEDATE: 2021/07/08; UPDATETIME: 17:22:43; USERCOMPTEXT3: TOSHIBA; VAL3: TTA005; VAL4: TOSHIBA
R1 = R: ADSMODELNAME: s_RL1632H_R001_JN; CDMASTERCADCELG: KC0020; CHIPSIZE: 3216; COMPONENTKIND: 0; COMPONENTNAME: R_R; COMPONENTTYPE: 4; FNLEADFREETHET1GT2GMCTH1: N_N_N; FUNCN: R_R; GCOUNT: 1; INSTANCENAME: INS575096; MAKER: KOA; MAXGCOUNT: 1; MOUNTINGFORMSMD: SMD; NOMINALRESISTAN: 1m; OUMECLASSIFICATION: \ÊÀpÅèïRí; OUMEMAKER: SSM iHÆ; OUMEMAKERKATAMEI: RL1632H-R001-JN; POWERRATING: 500m; QUADMODEL: RES_1M; RESISTANCETOLER: J; SIZECODESMD: 1608; TIME: 17:22:43; UPDATEDATE: 2021/07/08; UPDATETIME: 17:22:43; VAL1: 0; VAL3: RK73Z1JTTD; VAL4: KOA
R2 = R: ADSMODELNAME: s_RL1632H_R001_JN; CDMASTERCADCELG: KC0020; CHIPSIZE: 3216; COMPONENTKIND: 0; COMPONENTNAME: R_R; COMPONENTTYPE: 4; FNLEADFREETHET1GT2GMCTH1: N_N_N; FUNCN: R_R; GCOUNT: 1; INSTANCENAME: INS454341; MAKER: KOA; MAXGCOUNT: 1; MOUNTINGFORMSMD: SMD; NOMINALRESISTAN: 1m; OUMECLASSIFICATION: \ÊÀpÅèïRí; OUMEMAKER: SSM iHÆ; OUMEMAKERKATAMEI: RL1632H-R001-JN; POWERRATING: 500m; QUADMODEL: RES_1M; RESISTANCETOLER: J; SIZECODESMD: 1608; TIME: 17:22:43; UPDATEDATE: 2021/07/08; UPDATETIME: 17:22:43; VAL1: 1k(F); VAL2: 125mW; VAL3: RK73H1JTTD1001F; VAL4: KOA
R3 = R: ADSMODELNAME: s_RL1632H_R001_JN; CDMASTERCADCELG: KC0020; CHIPSIZE: 3216; COMPONENTKIND: 0; COMPONENTNAME: R_R; COMPONENTTYPE: 4; FNLEADFREETHET1GT2GMCTH1: N_N_N; FUNCN: R_R; GCOUNT: 1; INSTANCENAME: INS486568; MAKER: KOA; MAXGCOUNT: 1; MOUNTINGFORMSMD: SMD; NOMINALRESISTAN: 1m; OUMECLASSIFICATION: \ÊÀpÅèïRí; OUMEMAKER: SSM iHÆ; OUMEMAKERKATAMEI: RL1632H-R001-JN; POWERRATING: 500m; QUADMODEL: RES_1M; RESISTANCETOLER: J; SIZECODESMD: 1608; TIME: 17:22:43; UPDATEDATE: 2021/07/08; UPDATETIME: 17:22:43; VAL1: 10k(J); VAL2: 100mW; VAL3: RK73B1JTTD103J; VAL4: KOA
R4 = R: ADSMODELNAME: s_RL1632H_R001_JN; CDMASTERCADCELG: KC0020; CHIPSIZE: 3216; COMPONENTKIND: 0; COMPONENTNAME: R_R; COMPONENTTYPE: 4; FNLEADFREETHET1GT2GMCTH1: N_N_N; FUNCN: R_R; GCOUNT: 1; INSTANCENAME: INS471567; MAKER: KOA; MAXGCOUNT: 1; MOUNTINGFORMSMD: SMD; NOMINALRESISTAN: 1m; OUMECLASSIFICATION: \ÊÀpÅèïRí; OUMEMAKER: SSM iHÆ; OUMEMAKERKATAMEI: RL1632H-R001-JN; POWERRATING: 500m; QUADMODEL: RES_1M; RESISTANCETOLER: J; SIZECODESMD: 1608; TIME: 17:22:43; UPDATEDATE: 2021/07/08; UPDATETIME: 17:22:43; VAL1: 2.2k(F); VAL2: 100mW; VAL3: RK73H1JTTD2201F; VAL4: KOA
R5 = R: ADSMODELNAME: s_RL1632H_R001_JN; CDMASTERCADCELG: KC0020; CHIPSIZE: 3216; COMPONENTKIND: 0; COMPONENTNAME: R_R; COMPONENTTYPE: 4; FNLEADFREETHET1GT2GMCTH1: N_N_N; FUNCN: R_R; GCOUNT: 1; INSTANCENAME: INS487189; MAKER: KOA; MAXGCOUNT: 1; MOUNTINGFORMSMD: SMD; NOMINALRESISTAN: 1m; OUMECLASSIFICATION: \ÊÀpÅèïRí; OUMEMAKER: SSM iHÆ; OUMEMAKERKATAMEI: RL1632H-R001-JN; POWERRATING: 500m; QUADMODEL: RES_1M; RESISTANCETOLER: J; SIZECODESMD: 1608; TIME: 17:22:43; UPDATEDATE: 2021/07/08; UPDATETIME: 17:22:43; VAL1: 10k(J); VAL2: 100mW; VAL3: RK73B1JTTD103J; VAL4: KOA
R6 = R: ADSMODELNAME: s_RL1632H_R001_JN; CDMASTERCADCELG: KC0020; CHIPSIZE: 3216; COMPONENTKIND: 0; COMPONENTNAME: R_R; COMPONENTTYPE: 4; FNLEADFREETHET1GT2GMCTH1: N_N_N; FUNCN: R_R; GCOUNT: 1; INSTANCENAME: INS470310; MAKER: KOA; MAXGCOUNT: 1; MOUNTINGFORMSMD: SMD; NOMINALRESISTAN: 1m; OUMECLASSIFICATION: \ÊÀpÅèïRí; OUMEMAKER: SSM iHÆ; OUMEMAKERKATAMEI: RL1632H-R001-JN; POWERRATING: 500m; QUADMODEL: RES_1M; RESISTANCETOLER: J; SIZECODESMD: 1608; TIME: 17:22:43; UPDATEDATE: 2021/07/08; UPDATETIME: 17:22:43; VAL1: 2.2k(F); VAL2: 100mW; VAL3: RK73H1JTTD2201F; VAL4: KOA
R7 = R: ADSMODELNAME: s_RL1632H_R001_JN; CDMASTERCADCELG: KC0020; CHIPSIZE: 3216; COMPONENTKIND: 0; COMPONENTNAME: R_R; COMPONENTTYPE: 4; FNLEADFREETHET1GT2GMCTH1: N_N_N; FUNCN: R_R; GCOUNT: 1; INSTANCENAME: INS515728; MAKER: KOA; MAXGCOUNT: 1; MOUNTINGFORMSMD: SMD; NOMINALRESISTAN: 1m; OUMECLASSIFICATION: \ÊÀpÅèïRí; OUMEMAKER: SSM iHÆ; OUMEMAKERKATAMEI: RL1632H-R001-JN; POWERRATING: 500m; QUADMODEL: RES_1M; RESISTANCETOLER: J; SIZECODESMD: 1608; TIME: 17:22:43; UPDATEDATE: 2021/07/08; UPDATETIME: 17:22:43; VAL1: 10k(J); VAL2: 100mW; VAL3: RK73B1JTTD103J; VAL4: KOA
R8 = R: ADSMODELNAME: s_RL1632H_R001_JN; CDMASTERCADCELG: KC0020; CHIPSIZE: 3216; COMPONENTKIND: 0; COMPONENTNAME: R_R; COMPONENTTYPE: 4; FNLEADFREETHET1GT2GMCTH1: N_N_N; FUNCN: R_R; GCOUNT: 1; INSTANCENAME: INS593225; MAKER: KOA; MAXGCOUNT: 1; MOUNTINGFORMSMD: SMD; NOMINALRESISTAN: 1m; OUMECLASSIFICATION: \ÊÀpÅèïRí; OUMEMAKER: SSM iHÆ; OUMEMAKERKATAMEI: RL1632H-R001-JN; POWERRATING: 500m; QUADMODEL: RES_1M; RESISTANCETOLER: J; SIZECODESMD: 1608; TIME: 17:22:43; UPDATEDATE: 2021/07/08; UPDATETIME: 17:22:43; VAL1: 10k(J); VAL2: 100mW; VAL3: RK73B1JTTD103J; VAL4: KOA
R9 = R: ADSMODELNAME: s_RL1632H_R001_JN; CDMASTERCADCELG: KC0020; CHIPSIZE: 3216; COMPONENTKIND: 0; COMPONENTNAME: R_R; COMPONENTTYPE: 4; FNLEADFREETHET1GT2GMCTH1: N_N_N; FUNCN: R_R; GCOUNT: 1; INSTANCENAME: INS593358; MAKER: KOA; MAXGCOUNT: 1; MOUNTINGFORMSMD: SMD; NOMINALRESISTAN: 1m; OUMECLASSIFICATION: \ÊÀpÅèïRí; OUMEMAKER: SSM iHÆ; OUMEMAKERKATAMEI: RL1632H-R001-JN; POWERRATING: 500m; QUADMODEL: RES_1M; RESISTANCETOLER: J; SIZECODESMD: 1608; TIME: 17:22:43; UPDATEDATE: 2021/07/08; UPDATETIME: 17:22:43; VAL1: 10k(J); VAL2: 100mW; VAL3: RK73B1JTTD103J; VAL4: KOA
R10 = R: ADSMODELNAME: s_RL1632H_R001_JN; CDMASTERCADCELG: KC0020; CHIPSIZE: 3216; COMPONENTKIND: 0; COMPONENTNAME: R_R; COMPONENTTYPE: 4; FNLEADFREETHET1GT2GMCTH1: N_N_N; FUNCN: R_R; GCOUNT: 1; INSTANCENAME: INS593492; MAKER: KOA; MAXGCOUNT: 1; MOUNTINGFORMSMD: SMD; NOMINALRESISTAN: 1m; OUMECLASSIFICATION: \ÊÀpÅèïRí; OUMEMAKER: SSM iHÆ; OUMEMAKERKATAMEI: RL1632H-R001-JN; POWERRATING: 500m; QUADMODEL: RES_1M; RESISTANCETOLER: J; SIZECODESMD: 1608; TIME: 17:22:43; UPDATEDATE: 2021/07/08; UPDATETIME: 17:22:43; VAL1: 10k(J); VAL2: 100mW; VAL3: RK73B1JTTD103J; VAL4: KOA
R11 = R: ADSMODELNAME: s_RL1632H_R001_JN; CDMASTERCADCELG: KC0020; CHIPSIZE: 3216; COMPONENTKIND: 0; COMPONENTNAME: R_R; COMPONENTTYPE: 4; FNLEADFREETHET1GT2GMCTH1: N_N_N; FUNCN: R_R; GCOUNT: 1; INSTANCENAME: INS593627; MAKER: KOA; MAXGCOUNT: 1; MOUNTINGFORMSMD: SMD; NOMINALRESISTAN: 1m; OUMECLASSIFICATION: \ÊÀpÅèïRí; OUMEMAKER: SSM iHÆ; OUMEMAKERKATAMEI: RL1632H-R001-JN; POWERRATING: 500m; QUADMODEL: RES_1M; RESISTANCETOLER: J; SIZECODESMD: 1608; TIME: 17:22:43; UPDATEDATE: 2021/07/08; UPDATETIME: 17:22:43; VAL1: 10k(J); VAL2: 100mW; VAL3: RK73B1JTTD103J; VAL4: KOA
R12 = R: ADSMODELNAME: s_RL1632H_R001_JN; CDMASTERCADCELG: KC0020; CHIPSIZE: 3216; COMPONENTKIND: 0; COMPONENTNAME: R_R; COMPONENTTYPE: 4; FNLEADFREETHET1GT2GMCTH1: N_N_N; FUNCN: R_R; GCOUNT: 1; INSTANCENAME: INS561051; MAKER: KOA; MAXGCOUNT: 1; MOUNTINGFORMSMD: SMD; NOMINALRESISTAN: 1m; OUMECLASSIFICATION: \ÊÀpÅèïRí; OUMEMAKER: SSM iHÆ; OUMEMAKERKATAMEI: RL1632H-R001-JN; POWERRATING: 500m; QUADMODEL: RES_1M; RESISTANCETOLER: J; SIZECODESMD: 1608; TIME: 17:22:43; UPDATEDATE: 2021/07/08; UPDATETIME: 17:22:43; VAL1: 10k(J); VAL2: 100mW; VAL3: RK73B1JTTD103J; VAL4: KOA
R13 = R: ADSMODELNAME: s_RL1632H_R001_JN; CDMASTERCADCELG: KC0020; CHIPSIZE: 3216; COMPONENTKIND: 0; COMPONENTNAME: R_R; COMPONENTTYPE: 4; FNLEADFREETHET1GT2GMCTH1: N_N_N; FUNCN: R_R; GCOUNT: 1; INSTANCENAME: INS467908; MAKER: KOA; MAXGCOUNT: 1; MOUNTINGFORMSMD: SMD; NOMINALRESISTAN: 1m; OUMECLASSIFICATION: \ÊÀpÅèïRí; OUMEMAKER: SSM iHÆ; OUMEMAKERKATAMEI: RL1632H-R001-JN; POWERRATING: 500m; QUADMODEL: RES_1M; RESISTANCETOLER: J; SIZECODESMD: 1608; TIME: 17:22:43; UPDATEDATE: 2021/07/08; UPDATETIME: 17:22:43; VAL1: 1k(J); VAL2: 125mW; VAL3: RK73B1JTTD102J; VAL4: KOA
R14 = R: ADSMODELNAME: s_RL1632H_R001_JN; CDMASTERCADCELG: KC0020; CHIPSIZE: 3216; COMPONENTKIND: 0; COMPONENTNAME: R_R; COMPONENTTYPE: 4; FNLEADFREETHET1GT2GMCTH1: N_N_N; FUNCN: R_R; GCOUNT: 1; INSTANCENAME: INS467930; MAKER: KOA; MAXGCOUNT: 1; MOUNTINGFORMSMD: SMD; NOMINALRESISTAN: 1m; OUMECLASSIFICATION: \ÊÀpÅèïRí; OUMEMAKER: SSM iHÆ; OUMEMAKERKATAMEI: RL1632H-R001-JN; POWERRATING: 500m; QUADMODEL: RES_1M; RESISTANCETOLER: J; SIZECODESMD: 1608; TIME: 17:22:43; UPDATEDATE: 2021/07/08; UPDATETIME: 17:22:43; VAL1: 51k(J); VAL2: 100mW; VAL3: RK73B1JTTD513J; VAL4: KOA
R15 = R: ADSMODELNAME: s_RL1632H_R001_JN; CDMASTERCADCELG: KC0020; CHIPSIZE: 3216; COMPONENTKIND: 0; COMPONENTNAME: R_R; COMPONENTTYPE: 4; FNLEADFREETHET1GT2GMCTH1: N_N_N; FUNCN: R_R; GCOUNT: 1; INSTANCENAME: INS467952; MAKER: KOA; MAXGCOUNT: 1; MOUNTINGFORMSMD: SMD; NOMINALRESISTAN: 1m; OUMECLASSIFICATION: \ÊÀpÅèïRí; OUMEMAKER: SSM iHÆ; OUMEMAKERKATAMEI: RL1632H-R001-JN; POWERRATING: 500m; QUADMODEL: RES_1M; RESISTANCETOLER: J; SIZECODESMD: 1608; TIME: 17:22:43; UPDATEDATE: 2021/07/08; UPDATETIME: 17:22:43; VAL1: 130k(J); VAL2: 100mW; VAL3: RK73B1JTTD134J; VAL4: KOA
R16 = R: ADSMODELNAME: s_RL1632H_R001_JN; CDMASTERCADCELG: KC0020; CHIPSIZE: 3216; COMPONENTKIND: 0; COMPONENTNAME: R_R; COMPONENTTYPE: 4; FNLEADFREETHET1GT2GMCTH1: N_N_N; FUNCN: R_R; GCOUNT: 1; INSTANCENAME: INS467974; MAKER: KOA; MAXGCOUNT: 1; MOUNTINGFORMSMD: SMD; NOMINALRESISTAN: 1m; OUMECLASSIFICATION: \ÊÀpÅèïRí; OUMEMAKER: SSM iHÆ; OUMEMAKERKATAMEI: RL1632H-R001-JN; POWERRATING: 500m; QUADMODEL: RES_1M; RESISTANCETOLER: J; SIZECODESMD: 1608; TIME: 17:22:43; UPDATEDATE: 2021/07/08; UPDATETIME: 17:22:43; VAL1: 270k(J); VAL2: 100mW; VAL3: RK73B1JTTD274J; VAL4: KOA
R34 = R: CDBNAME: R1206; COMPONENTKIND: 0; COMPONENTNAME: R_R; COMPONENTTYPE: 4; FUNCN: R_R; INSTANCENAME: cmp140; SIZECODESMD: 3216; TIME: 17:22:43; UPDATEDATE: 2021/07/08; UPDATETIME: 17:22:43; VAL1: 470m(F); VAL2: 0.5W; VAL3: ERJ8BQFR47V; VAL4: Panasonic
R35 = R: ADSMODELNAME: s_RL1632H_R001_JN; CDMASTERCADCELG: KC0020; CHIPSIZE: 3216; COMPONENTKIND: 0; COMPONENTNAME: R_R; COMPONENTTYPE: 4; FNLEADFREETHET1GT2GMCTH1: N_N_N; FUNCN: R_R; GCOUNT: 1; INSTANCENAME: INS628941; MAKER: KOA; MAXGCOUNT: 1; MOUNTINGFORMSMD: SMD; NOMINALRESISTAN: 1m; NOTMOUNT: NOT MOUNT; OUMECLASSIFICATION: \ÊÀpÅèïRí; OUMEMAKER: SSM iHÆ; OUMEMAKERKATAMEI: RL1632H-R001-JN; POWERRATING: 500m; QUADMODEL: RES_1M; RESISTANCETOLER: J; SIZECODESMD: 1608; TIME: 17:22:43; UPDATEDATE: 2021/07/08; UPDATETIME: 17:22:43; VAL1: 0; VAL3: RK73Z1JTTD; VAL4: KOA
R36 = R: ADSMODELNAME: s_RL1632H_R001_JN; CDMASTERCADCELG: KC0020; CHIPSIZE: 3216; COMPONENTKIND: 0; COMPONENTNAME: R_R; COMPONENTTYPE: 4; FNLEADFREETHET1GT2GMCTH1: N_N_N; FUNCN: R_R; GCOUNT: 1; INSTANCENAME: INS628993; MAKER: KOA; MAXGCOUNT: 1; MOUNTINGFORMSMD: SMD; NOMINALRESISTAN: 1m; OUMECLASSIFICATION: \ÊÀpÅèïRí; OUMEMAKER: SSM iHÆ; OUMEMAKERKATAMEI: RL1632H-R001-JN; POWERRATING: 500m; QUADMODEL: RES_1M; RESISTANCETOLER: J; SIZECODESMD: 1608; TIME: 17:22:43; UPDATEDATE: 2021/07/08; UPDATETIME: 17:22:43; VAL1: 0; VAL3: RK73Z1JTTD; VAL4: KOA
R37 = R: ADSMODELNAME: s_RL1632H_R001_JN; CDMASTERCADCELG: KC0020; CHIPSIZE: 3216; COMPONENTKIND: 0; COMPONENTNAME: R_R; COMPONENTTYPE: 4; FNLEADFREETHET1GT2GMCTH1: N_N_N; FUNCN: R_R; GCOUNT: 1; INSTANCENAME: INS629194; MAKER: KOA; MAXGCOUNT: 1; MOUNTINGFORMSMD: SMD; NOMINALRESISTAN: 1m; OUMECLASSIFICATION: \ÊÀpÅèïRí; OUMEMAKER: SSM iHÆ; OUMEMAKERKATAMEI: RL1632H-R001-JN; POWERRATING: 500m; QUADMODEL: RES_1M; RESISTANCETOLER: J; SIZECODESMD: 1608; TIME: 17:22:43; UPDATEDATE: 2021/07/08; UPDATETIME: 17:22:43; VAL1: 0; VAL3: RK73Z1JTTD; VAL4: KOA
R38 = R: ADSMODELNAME: s_RL1632H_R001_JN; CDMASTERCADCELG: KC0020; CHIPSIZE: 3216; COMPONENTKIND: 0; COMPONENTNAME: R_R; COMPONENTTYPE: 4; FNLEADFREETHET1GT2GMCTH1: N_N_N; FUNCN: R_R; GCOUNT: 1; INSTANCENAME: INS629216; MAKER: KOA; MAXGCOUNT: 1; MOUNTINGFORMSMD: SMD; NOMINALRESISTAN: 1m; OUMECLASSIFICATION: \ÊÀpÅèïRí; OUMEMAKER: SSM iHÆ; OUMEMAKERKATAMEI: RL1632H-R001-JN; POWERRATING: 500m; QUADMODEL: RES_1M; RESISTANCETOLER: J; SIZECODESMD: 1608; TIME: 17:22:43; UPDATEDATE: 2021/07/08; UPDATETIME: 17:22:43; VAL1: 0; VAL3: RK73Z1JTTD; VAL4: KOA
R39 = R: ADSMODELNAME: s_RL1632H_R001_JN; CDMASTERCADCELG: KC0020; CHIPSIZE: 3216; COMPONENTKIND: 0; COMPONENTNAME: R_R; COMPONENTTYPE: 4; FNLEADFREETHET1GT2GMCTH1: N_N_N; FUNCN: R_R; GCOUNT: 1; INSTANCENAME: INS634861; MAKER: KOA; MAXGCOUNT: 1; MOUNTINGFORMSMD: SMD; NOMINALRESISTAN: 1m; NOTMOUNT: NOT MOUNT; OUMECLASSIFICATION: \ÊÀpÅèïRí; OUMEMAKER: SSM iHÆ; OUMEMAKERKATAMEI: RL1632H-R001-JN; POWERRATING: 500m; QUADMODEL: RES_1M; RESISTANCETOLER: J; SIZECODESMD: 1608; TIME: 17:22:43; UPDATEDATE: 2021/07/08; UPDATETIME: 17:22:43; VAL1: 0; VAL3: RK73Z1JTTD; VAL4: KOA
R40 = R_0: ADSMODELNAME: s_RL1632H_R001_JN; CDMASTERCADCELG: KC0020; CHIPSIZE: 3216; COMPONENTKIND: 0; COMPONENTNAME: R_0_R_0; COMPONENTTYPE: 4; FNLEADFREETHET1GT2GMCTH1: N_N_N; FUNCN: R_0_R_0; GCOUNT: 1; INSTANCENAME: INS642505; MAKER: KOA; MAXGCOUNT: 1; MOUNTINGFORMSMD: SMD; NOMINALRESISTAN: 1m; OUMECLASSIFICATION: \ÊÀpÅèïRí; OUMEMAKER: SSM iHÆ; OUMEMAKERKATAMEI: RL1632H-R001-JN; POWERRATING: 500m; QUADMODEL: RES_1M; RESISTANCETOLER: J; SIZECODESMD: 1608; VAL1: 330(J); VAL2: 125mW; VAL3: RK73B1JTTD331J; VAL4: KOA
R41 = R_0: ADSMODELNAME: s_RL1632H_R001_JN; CDMASTERCADCELG: KC0020; CHIPSIZE: 3216; COMPONENTKIND: 0; COMPONENTNAME: R_0_R_0; COMPONENTTYPE: 4; FNLEADFREETHET1GT2GMCTH1: N_N_N; FUNCN: R_0_R_0; GCOUNT: 1; INSTANCENAME: INS642429; MAKER: KOA; MAXGCOUNT: 1; MOUNTINGFORMSMD: SMD; NOMINALRESISTAN: 1m; OUMECLASSIFICATION: \ÊÀpÅèïRí; OUMEMAKER: SSM iHÆ; OUMEMAKERKATAMEI: RL1632H-R001-JN; POWERRATING: 500m; QUADMODEL: RES_1M; RESISTANCETOLER: J; SIZECODESMD: 1608; VAL1: 330(J); VAL2: 125mW; VAL3: RK73B1JTTD331J; VAL4: KOA
R42 = R_0: ADSMODELNAME: s_RL1632H_R001_JN; CDMASTERCADCELG: KC0020; CHIPSIZE: 3216; COMPONENTKIND: 0; COMPONENTNAME: R_0_R_0; COMPONENTTYPE: 4; FNLEADFREETHET1GT2GMCTH1: N_N_N; FUNCN: R_0_R_0; GCOUNT: 1; INSTANCENAME: INS642303; MAKER: KOA; MAXGCOUNT: 1; MOUNTINGFORMSMD: SMD; NOMINALRESISTAN: 1m; OUMECLASSIFICATION: \ÊÀpÅèïRí; OUMEMAKER: SSM iHÆ; OUMEMAKERKATAMEI: RL1632H-R001-JN; POWERRATING: 500m; QUADMODEL: RES_1M; RESISTANCETOLER: J; SIZECODESMD: 1608; VAL1: 330(J); VAL2: 125mW; VAL3: RK73B1JTTD331J; VAL4: KOA
R43 = R_0: ADSMODELNAME: s_RL1632H_R001_JN; CDMASTERCADCELG: KC0020; CHIPSIZE: 3216; COMPONENTKIND: 0; COMPONENTNAME: R_0_R_0; COMPONENTTYPE: 4; FNLEADFREETHET1GT2GMCTH1: N_N_N; FUNCN: R_0_R_0; GCOUNT: 1; INSTANCENAME: INS642261; MAKER: KOA; MAXGCOUNT: 1; MOUNTINGFORMSMD: SMD; NOMINALRESISTAN: 1m; OUMECLASSIFICATION: \ÊÀpÅèïRí; OUMEMAKER: SSM iHÆ; OUMEMAKERKATAMEI: RL1632H-R001-JN; POWERRATING: 500m; QUADMODEL: RES_1M; RESISTANCETOLER: J; SIZECODESMD: 1608; VAL1: 330(J); VAL2: 125mW; VAL3: RK73B1JTTD331J; VAL4: KOA
R44 = R_0: ADSMODELNAME: s_RL1632H_R001_JN; CDMASTERCADCELG: KC0020; CHIPSIZE: 3216; COMPONENTKIND: 0; COMPONENTNAME: R_0_R_0; COMPONENTTYPE: 4; FNLEADFREETHET1GT2GMCTH1: N_N_N; FUNCN: R_0_R_0; GCOUNT: 1; INSTANCENAME: INS642387; MAKER: KOA; MAXGCOUNT: 1; MOUNTINGFORMSMD: SMD; NOMINALRESISTAN: 1m; OUMECLASSIFICATION: \ÊÀpÅèïRí; OUMEMAKER: SSM iHÆ; OUMEMAKERKATAMEI: RL1632H-R001-JN; POWERRATING: 500m; QUADMODEL: RES_1M; RESISTANCETOLER: J; SIZECODESMD: 1608; VAL1: 330(J); VAL2: 125mW; VAL3: RK73B1JTTD331J; VAL4: KOA
R45 = R_0: ADSMODELNAME: s_RL1632H_R001_JN; CDMASTERCADCELG: KC0020; CHIPSIZE: 3216; COMPONENTKIND: 0; COMPONENTNAME: R_0_R_0; COMPONENTTYPE: 4; FNLEADFREETHET1GT2GMCTH1: N_N_N; FUNCN: R_0_R_0; GCOUNT: 1; INSTANCENAME: INS642773; MAKER: KOA; MAXGCOUNT: 1; MOUNTINGFORMSMD: SMD; NOMINALRESISTAN: 1m; OUMECLASSIFICATION: \ÊÀpÅèïRí; OUMEMAKER: SSM iHÆ; OUMEMAKERKATAMEI: RL1632H-R001-JN; POWERRATING: 500m; QUADMODEL: RES_1M; RESISTANCETOLER: J; SIZECODESMD: 1608; VAL1: 330(J); VAL2: 125mW; VAL3: RK73B1JTTD331J; VAL4: KOA
SW1 = 154ANS_0: COMPONENTKIND: 117; COMPONENTNAME: 154ANS_0_154ANS_0; COMPONENTTYPE: 4; FUNCN: 154ANS_0_154ANS_0; INSTANCENAME: INS614366; VAL2: 28VDC/0.4VA; VAL3: B12AP; VAL4: NKK
SW2 = 154ANS_0: COMPONENTKIND: 117; COMPONENTNAME: 154ANS_0_154ANS_0; COMPONENTTYPE: 4; FUNCN: 154ANS_0_154ANS_0; INSTANCENAME: INS473874; VAL2: 28VDC/0.4VA; VAL3: B12AP; VAL4: NKK
SW3 = 154ANS_0: COMPONENTKIND: 117; COMPONENTNAME: 154ANS_0_154ANS_0; COMPONENTTYPE: 4; FUNCN: 154ANS_0_154ANS_0; INSTANCENAME: INS614843; VAL2: 28VDC/0.4VA; VAL3: B12AP; VAL4: NKK
SW4 = 154ANS_0: COMPONENTKIND: 117; COMPONENTNAME: 154ANS_0_154ANS_0; COMPONENTTYPE: 4; FUNCN: 154ANS_0_154ANS_0; INSTANCENAME: INS614962; VAL2: 28VDC/0.4VA; VAL3: B12AP; VAL4: NKK
SW5 = 154ANS_0: COMPONENTKIND: 117; COMPONENTNAME: 154ANS_0_154ANS_0; COMPONENTTYPE: 4; FUNCN: 154ANS_0_154ANS_0; INSTANCENAME: INS615081; VAL2: 28VDC/0.4VA; VAL3: B12AP; VAL4: NKK
SW6 = 154ANS_0: COMPONENTKIND: 117; COMPONENTNAME: 154ANS_0_154ANS_0; COMPONENTTYPE: 4; FUNCN: 154ANS_0_154ANS_0; INSTANCENAME: INS615857; VAL2: 28VDC/0.4VA; VAL3: B12AP; VAL4: NKK
SW7 = 154ANS_2: COMPONENTKIND: 117; COMPONENTNAME: 154ANS_2_154ANS_2; COMPONENTTYPE: 4; FUNCN: 154ANS_2_154ANS_2; INSTANCENAME: INS469431; VAL3: S-2150; VAL4: Nidec Copal
U?#2 = WAKU_DEF100_1: AUTHOR: t5459927; COMPONENTTYPE: 2; DATE: 2017/06/06; DESIGNED: TOSHIBA; DRAWINGNUMBER: RD245; FUNCTION: Gate Driver and MOSFETs; INSTANCENAME: INS636826; PAGENUMBER: 8; REVISION: 01; SHEETNUMBER: 1/2; SHTSAVECOUNT: 36; TITLE: Automotive Brushed DC Motor Control / Circuit Using TB9103FTG; UPDATEDATE: 2024/10/02; UPDATETIME: 10:40:02; UPDATEUSER: sptcae09

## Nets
D5V: C9.2 D2.K D3.K IC1.1(VCC) Q11.S Q12.S R2.1 R3.1 R5.1 SW1.1(NC) SW2.1(NC) SW3.1(NC) SW4.1(NC) SW5.1(NC) SW6.1(NC)
GND: C1.2 C2.1 C3.1 C4.1 C5.1 C6.1 C7.1 C8.1 C9.1 C10.1 C13.1 C14.1 C16.2 C17.1 CN1.2 CN2.10 CN3.3 CN4.2 DZ1.A IC1.20(GND) IC1.EPAD(E-PAD) IC2.10(GND1) IC2.14(TP1) IC2.16(TP2) IC2.20(GND2) LED1.K LED2.K LED3.K Q2.1 Q2.2 Q2.3 Q4.1 Q4.2 Q4.3 Q6.1 Q6.2 Q6.3 Q8.1 Q8.2 Q8.3 R13.2 R14.2 R15.2 R16.2 R18.2 R26.1 R27.2 R32.1 R33.2 R37.1 R38.1 R39.1 SW1.3(NO) SW2.3(NO) SW3.3(NO) SW4.3(NO) SW5.3(NO) SW6.3(NO)
VBAT: C1.1 CN1.1 D4.K Q9.1 Q9.2 Q9.3 R19.1
DIAG1: CN2.4 IC1.2(DIAG1) Q11.G R3.2
DIAG2: CN2.6 IC1.3(DIAG2) Q12.G R5.2
GH2: IC1.7(GH2) R28.2
GL2: IC1.5(GL2) R31.2
IN1: C5.2 IC1.21(IN1) R8.2 R41.1
IN2: C6.2 IC1.22(IN2) R9.2 R42.1
IN3: C7.2 IC1.23(IN3) R10.2 R43.1
IN4: C8.2 IC1.24(IN4) R11.2 R44.1
MODE: C17.2 IC1.17(MODE) R12.2 R45.2
NSLEEP: C4.2 IC1.19(nSLEEP) R7.2 R40.1
OUT1: CN3.1 Q1.1 Q1.2 Q1.3 Q2.5 Q2.6 Q2.7 Q2.8 Q5.1 Q5.2 Q5.3 Q6.5 Q6.6 Q6.7 Q6.8 R23.1 R24.2
OUT2: CN3.2 Q3.1 Q3.2 Q3.3 Q4.5 Q4.6 Q4.7 Q4.8 Q7.1 Q7.2 Q7.3 Q8.5 Q8.6 Q8.7 Q8.8 R29.1 R30.2
SH2: IC1.6(SH2) R29.2
SIG0011: IC1.9(GH1) R22.2
SIG0012: IC1.10(SH1) R23.2
SIG0013: IC1.11(GL1) R25.2
SIG595: CN4.4 IC2.13(SE) R35.1 R37.2
SIG638: IC2.3(OUT) Q13.B
SIG639: IC2.2(VS) Q13.E R34.2
SIG642: CN4.5 IC2.19(WS) R36.1 R39.2
SIG643: CN4.6 IC2.17(CK) R38.2
VB: C2.2 C10.2 C11.2 C13.2 C14.2 DZ1.C IC1.18(VB) IC2.1(VIN) Q1.5 Q1.6 Q1.7 Q1.8 Q3.5 Q3.6 Q3.7 Q3.8 Q5.5 Q5.6 Q5.7 Q5.8 Q7.5 Q7.6 Q7.7 Q7.8 Q9.5 Q9.6 Q9.7 Q9.8 R21.1 R34.1
VDS: IC1.15(VDS) SW7.C(NO)
VEXT: CN2.2 D2.A
N03760: CN2.8 R45.1
N03763: LED1.A R2.2
N03764: LED2.A R4.2
N03765: C15.2 IC2.5(COMP)
N469486: R16.1 SW7.4(NO)
N469495: R15.1 SW7.3(NO)
N469504: R14.1 SW7.2(COMMON)
N469513: R13.1 SW7.1(NC)
N470308: Q12.D R6.1
N470324: LED3.A R6.2
N471565: Q11.D R4.1
N500947: Q9.4 Q10.C R19.2 R20.1
N500987: C11.1 IC1.13(VCP) R20.2
N501039: C12.2 IC1.14(CP)
N501211: C12.1 R17.1
N501689: Q1.4 Q5.4 R22.1 R24.1
N501775: IC1.12(SL1) R26.2
N502037: IC1.4(SL2) R32.2
N502087: Q2.4 Q6.4 R25.1 R27.1
N533770: Q4.4 Q8.4 R31.1 R33.1
N554303: Q3.4 Q7.4 R28.1 R30.1
N561074: R12.1 SW6.2(COMMON)
N573754: R7.1 SW1.2(COMMON)
N575579: IC1.16(CPD) R17.2
N576851: IC1.8(DH) R21.2
N593239: R8.1 SW2.2(COMMON)
N593372: R9.1 SW3.2(COMMON)
N593506: R10.1 SW4.2(COMMON)
N593641: R11.1 SW5.2(COMMON)
N607694: Q10.B R18.1
N610543: D4.A Q10.E
N622087: C3.2 C15.1 CN4.1 IC2.7(VCCS) IC2.8(VCC) Q13.C R1.1 R35.2 R36.2
N622351: C16.1 IC2.15(TC)
N628803: CN4.3 IC2.11(#RESET)
N665551: D3.A R1.2
N4658670: CN2.1 R40.2
N4658672: CN2.3 R41.2
N4658674: CN2.5 R42.2
N4658676: CN2.7 R43.2
N4658678: CN2.9 R44.2

Not connected (* = marked no-connect by the designer): IC2 4 6 9 12 18

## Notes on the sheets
sheet 1
- VBAT Input
- External MCU Control
- 5V Power Supply
- 5V
- GND
- RESET
- SE
- WS
- CK
- From Gate Driver
- To Gate Driver
sheet 2
- Reverse Connection
     Protector
- Motor Output
- EPAD
- Gate Driver
- Q1, Q2, Q3, Q4: Using TSON Advance(WF) Package MOSFET
  Q5, Q6, Q7, Q8: Using SOP Advance(WF) Package MOSFET
